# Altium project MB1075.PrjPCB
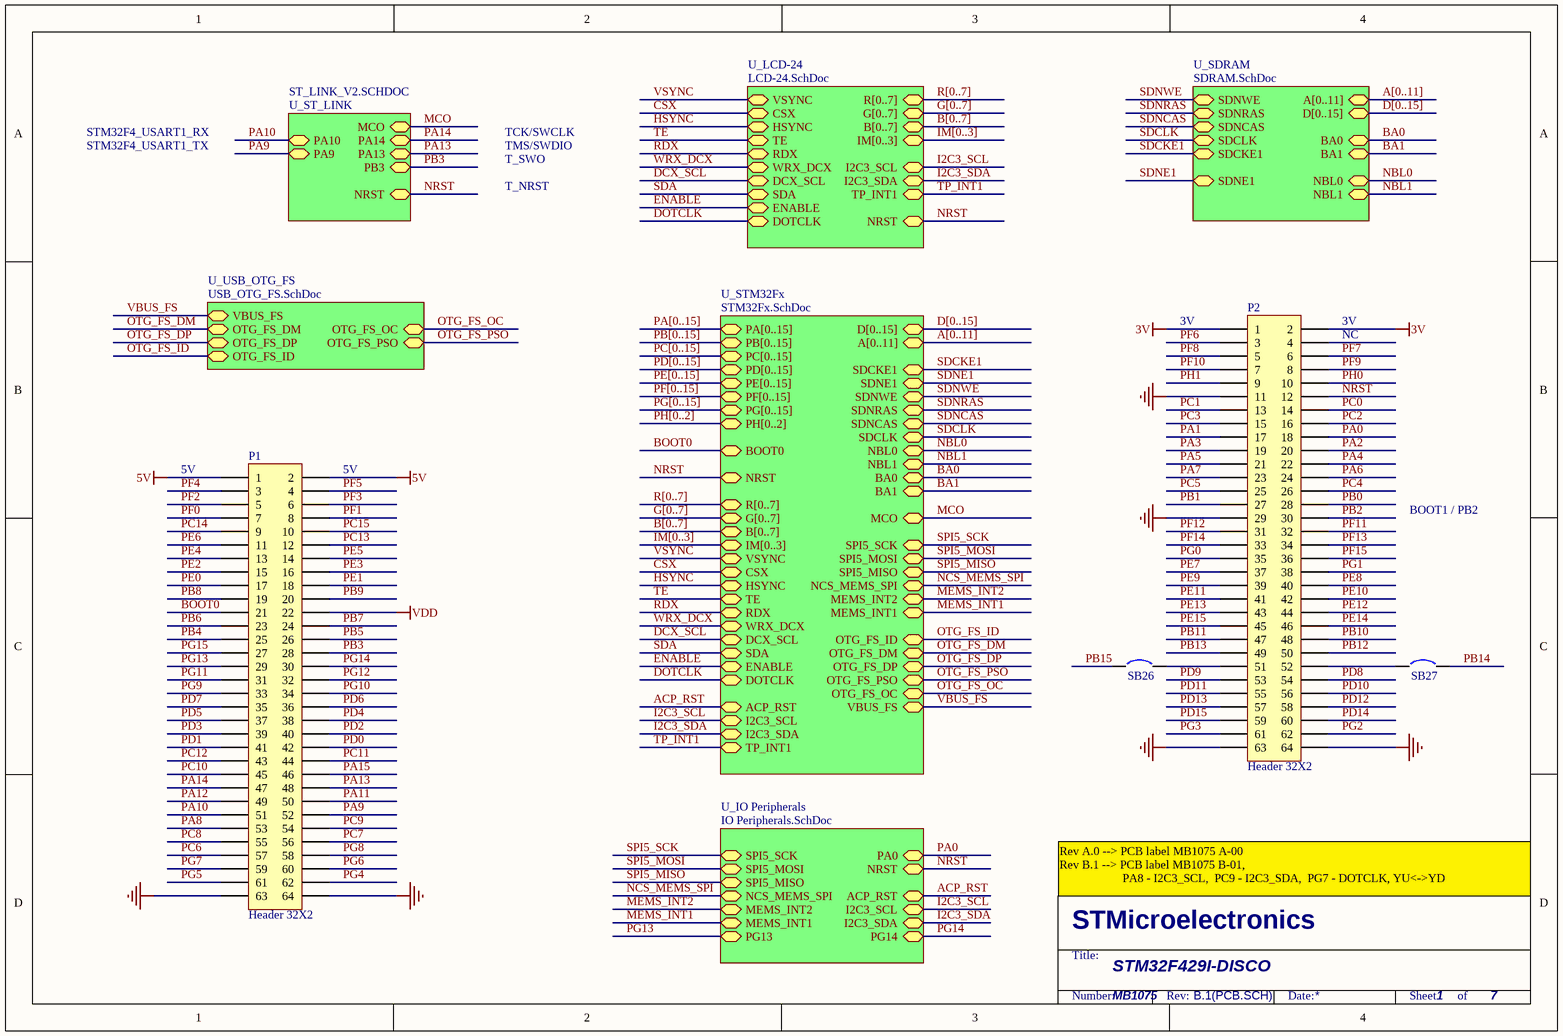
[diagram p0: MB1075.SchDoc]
7 sheets, 189 parts. Net scope: hierarchical (ports join the sheet entries above them; power ports are global).
Sheets:
  MB1075.SchDoc
    U_SDRAM = SDRAM.SchDoc
    U_IO Peripherals = IO Peripherals.SchDoc
    U_STM32Fx = STM32Fx.SchDoc
    U_USB_OTG_FS = USB_OTG_FS.SchDoc
    U_ST_LINK = ST_LINK_V2.SCHDOC
    U_LCD-24 = LCD-24.SchDoc

## Sheet MB1075.SchDoc
size A4; DocumentNumber: 1; Revision: B.1(PCB.SCH); SheetNumber: 1; SheetTotal: 7; PageSetup: Record=PageOptions|CenterHorizontal=True|CenterVertical=True|PrintScale=1.00|XCorrection=1.00|YCorrection=1.00|PrintKind=1|BorderSize=5000000|LeftOffset=0|BottomOffset=0|Orientation=2|PaperLength=1000|PaperWidth=1000|Scale=100|PaperSource=15|PrintQuality=1200|MediaType=1|DitherType=10|PaperKind=A4|PrintScaleMode=1

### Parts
P1  Header 32X2  [HDR2X32]
P2  Header 32X2  [HDR2X32]
SB26  Circuit Breaker  [JP2_SMD]  (value not drawn)
SB27  Circuit Breaker  [JP2_SMD]  (value not drawn)

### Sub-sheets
U_IO Peripherals = IO Peripherals.SchDoc: PA0, NRST, MEMS_INT1, NCS_MEMS_SPI, MEMS_INT2, SPI5_SCK, SPI5_MISO, SPI5_MOSI, ACP_RST, I2C3_SCL, I2C3_SDA, PG13, PG14
U_LCD-24 = LCD-24.SchDoc: NRST, B[0..7], G[0..7], R[0..7], IM[0..3], TP_INT1, VSYNC, CSX, HSYNC, TE, WRX_DCX, RDX, ENABLE, DCX_SCL, SDA, I2C3_SCL, I2C3_SDA, DOTCLK
U_SDRAM = SDRAM.SchDoc: A[0..11], D[0..15], SDNE1, NBL1, NBL0, SDNWE, SDNRAS, SDNCAS, SDCLK, SDCKE1, BA0, BA1
U_ST_LINK = ST_LINK_V2.SCHDOC: PA13, PA14, NRST, PB3, MCO, PA10, PA9
U_STM32Fx = STM32Fx.SchDoc: BOOT0, NRST, MCO, D[0..15], A[0..11], SDCKE1, SDNE1, SDNWE, NBL0, SDNRAS, NBL1, SDCLK, SDNCAS, BA0, BA1, PA[0..15], PB[0..15], PC[0..15], PD[0..15], PE[0..15], PH[0..2], PF[0..15], PG[0..15], R[0..7], G[0..7], B[0..7], IM[0..3], TP_INT1, VSYNC, CSX, HSYNC, TE, WRX_DCX, RDX, ENABLE, DCX_SCL, SDA, I2C3_SCL, I2C3_SDA, ACP_RST, MEMS_INT1, NCS_MEMS_SPI, MEMS_INT2, SPI5_SCK, SPI5_MISO, SPI5_MOSI, OTG_FS_ID, OTG_FS_DM, OTG_FS_DP, OTG_FS_PSO, OTG_FS_OC, VBUS_FS, DOTCLK
U_USB_OTG_FS = USB_OTG_FS.SchDoc: OTG_FS_PSO, OTG_FS_OC, OTG_FS_DM, OTG_FS_DP, OTG_FS_ID, VBUS_FS

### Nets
3V: P2.1 P2.2
5V: P1.1 P1.2
GND: P1.63 P1.64 P2.11 P2.29 P2.63 P2.64
VDD: P1.22
ACP_RST: P2.23 ; sheet U_IO Peripherals/ACP_RST, sheet U_STM32Fx/ACP_RST  [also labelled PA7]
BA0: P1.62 ; sheet U_SDRAM/BA0, sheet U_STM32Fx/BA0  [also labelled PG4]
BA1: P1.61 ; sheet U_SDRAM/BA1, sheet U_STM32Fx/BA1  [also labelled PG5]
BOOT0: P1.21 ; sheet U_STM32Fx/BOOT0
CSX: P2.16 ; sheet U_STM32Fx/CSX, sheet U_LCD-24/CSX  [also labelled PC2]
DCX_SCL: P2.6 ; sheet U_IO Peripherals/SPI5_SCK, sheet U_STM32Fx/DCX_SCL, sheet U_STM32Fx/SPI5_SCK, sheet U_LCD-24/DCX_SCL  [also labelled PF7, SPI5_SCK]
DOTCLK: P1.59 ; sheet U_STM32Fx/DOTCLK, sheet U_LCD-24/DOTCLK  [also labelled PG7]
ENABLE: P2.7 ; sheet U_STM32Fx/ENABLE, sheet U_LCD-24/ENABLE  [also labelled PF10]
HSYNC: P1.57 ; sheet U_STM32Fx/HSYNC, sheet U_LCD-24/HSYNC  [also labelled PC6]
I2C3_SCL: P1.53 ; sheet U_IO Peripherals/I2C3_SCL, sheet U_STM32Fx/I2C3_SCL, sheet U_LCD-24/I2C3_SCL  [also labelled PA8]
I2C3_SDA: P1.54 ; sheet U_IO Peripherals/I2C3_SDA, sheet U_STM32Fx/I2C3_SDA, sheet U_LCD-24/I2C3_SDA  [also labelled PC9]
MCO: sheet U_STM32Fx/MCO, sheet U_ST_LINK/MCO
MEMS_INT1: P2.17 ; sheet U_IO Peripherals/MEMS_INT1, sheet U_STM32Fx/MEMS_INT1  [also labelled PA1]
MEMS_INT2: P2.20 ; sheet U_IO Peripherals/MEMS_INT2, sheet U_STM32Fx/MEMS_INT2  [also labelled PA2]
NBL0: P1.17 ; sheet U_SDRAM/NBL0, sheet U_STM32Fx/NBL0  [also labelled PE0]
NBL1: P1.18 ; sheet U_SDRAM/NBL1, sheet U_STM32Fx/NBL1  [also labelled PE1]
NCS_MEMS_SPI: P2.13 ; sheet U_IO Peripherals/NCS_MEMS_SPI, sheet U_STM32Fx/NCS_MEMS_SPI  [also labelled PC1]
NRST: P2.12 ; sheet U_IO Peripherals/NRST, sheet U_STM32Fx/NRST, sheet U_ST_LINK/NRST, sheet U_LCD-24/NRST
OTG_FS_DM: SB27.2 ; sheet U_STM32Fx/OTG_FS_DM, sheet U_USB_OTG_FS/OTG_FS_DM  [also labelled PB14]
OTG_FS_DP: SB26.1 ; sheet U_STM32Fx/OTG_FS_DP, sheet U_USB_OTG_FS/OTG_FS_DP  [also labelled PB15]
OTG_FS_ID: P2.50 ; sheet U_STM32Fx/OTG_FS_ID, sheet U_USB_OTG_FS/OTG_FS_ID  [also labelled PB12]
OTG_FS_OC: P2.25 ; sheet U_STM32Fx/OTG_FS_OC, sheet U_USB_OTG_FS/OTG_FS_OC  [also labelled PC5]
OTG_FS_PSO: P2.26 ; sheet U_STM32Fx/OTG_FS_PSO, sheet U_USB_OTG_FS/OTG_FS_PSO  [also labelled PC4]
PA0: P2.18 ; sheet U_IO Peripherals/PA0
PA3: P2.19  [project net B5]
PA4: P2.22 ; sheet U_STM32Fx/VSYNC, sheet U_LCD-24/VSYNC  [also labelled VSYNC]
PA5: P2.21
PA6: P2.24  [project net G2]
PA9: P1.52 ; sheet U_ST_LINK/PA9
PA10: P1.51 ; sheet U_ST_LINK/PA10
PA11: P1.50
PA12: P1.49
PA13: P1.48 ; sheet U_ST_LINK/PA13
PA14: P1.47 ; sheet U_ST_LINK/PA14
PA15: P1.46 ; sheet U_STM32Fx/TP_INT1, sheet U_LCD-24/TP_INT1  [also labelled TP_INT1]
PB0: P2.28
PB1: P2.27
PB2: P2.30
PB3: P1.28 ; sheet U_ST_LINK/PB3
PB4: P1.25
PB5: P1.26 ; sheet U_SDRAM/SDCKE1, sheet U_STM32Fx/SDCKE1  [also labelled SDCKE1]
PB6: P1.23 ; sheet U_SDRAM/SDNE1, sheet U_STM32Fx/SDNE1  [also labelled SDNE1]
PB7: P1.24
PB8: P1.19  [project net B6]
PB9: P1.20  [project net B7]
PB10: P2.48  [project net G4]
PB11: P2.47  [project net G5]
PB13: P2.49 ; sheet U_STM32Fx/VBUS_FS, sheet U_USB_OTG_FS/VBUS_FS  [also labelled VBUS_FS]
PC0: P2.14 ; sheet U_SDRAM/SDNWE, sheet U_STM32Fx/SDNWE  [also labelled SDNWE]
PC3: P2.15
PC7: P1.56  [project net G6]
PC8: P1.55
PC10: P1.45
PC11: P1.44
PC12: P1.43
PC13: P1.12
PC14: P1.9
PC15: P1.10
PD0: P1.42  [project net D2]
PD1: P1.41  [project net D3]
PD2: P1.40
PD3: P1.39  [project net G7]
PD4: P1.38
PD5: P1.37
PD6: P1.36  [project net B2]
PD7: P1.35
PD8: P2.54  [project net D13]
PD9: P2.53  [project net D14]
PD10: P2.56  [project net D15]
PD11: P2.55 ; sheet U_STM32Fx/TE, sheet U_LCD-24/TE  [also labelled TE]
PD12: P2.58 ; sheet U_STM32Fx/RDX, sheet U_LCD-24/RDX  [also labelled RDX]
PD13: P2.57 ; sheet U_STM32Fx/WRX_DCX, sheet U_LCD-24/WRX_DCX  [also labelled WRX_DCX]
PD14: P2.60  [project net D0]
PD15: P2.59  [project net D1]
PE2: P1.15
PE3: P1.16
PE4: P1.13
PE5: P1.14
PE6: P1.11
PE7: P2.37  [project net D4]
PE8: P2.40  [project net D5]
PE9: P2.39  [project net D6]
PE10: P2.42  [project net D7]
PE11: P2.41  [project net D8]
PE12: P2.44  [project net D9]
PE13: P2.43  [project net D10]
PE14: P2.46  [project net D11]
PE15: P2.45  [project net D12]
PF0: P1.7  [project net A0]
PF1: P1.8  [project net A1]
PF2: P1.5  [project net A2]
PF3: P1.6  [project net A3]
PF4: P1.3  [project net A4]
PF5: P1.4  [project net A5]
PF6: P2.3
PF8: P2.5 ; sheet U_IO Peripherals/SPI5_MISO, sheet U_STM32Fx/SPI5_MISO  [also labelled SPI5_MISO]
PF9: P2.8 ; sheet U_IO Peripherals/SPI5_MOSI, sheet U_STM32Fx/SDA, sheet U_STM32Fx/SPI5_MOSI, sheet U_LCD-24/SDA  [also labelled SDA, SPI5_MOSI]
PF11: P2.32 ; sheet U_SDRAM/SDNRAS, sheet U_STM32Fx/SDNRAS  [also labelled SDNRAS]
PF12: P2.31  [project net A6]
PF13: P2.34  [project net A7]
PF14: P2.33  [project net A8]
PF15: P2.36  [project net A9]
PG0: P2.35  [project net A10]
PG1: P2.38  [project net A11]
PG2: P2.62
PG3: P2.61
PG6: P1.60
PG8: P1.58 ; sheet U_SDRAM/SDCLK, sheet U_STM32Fx/SDCLK  [also labelled SDCLK]
PG9: P1.33
PG10: P1.34  [project net G3]
PG11: P1.31  [project net B3]
PG12: P1.32  [project net B4]
PG13: P1.29 ; sheet U_IO Peripherals/PG13
PG14: P1.30 ; sheet U_IO Peripherals/PG14
PG15: P1.27 ; sheet U_SDRAM/SDNCAS, sheet U_STM32Fx/SDNCAS  [also labelled SDNCAS]
PH0: P2.10
PH1: P2.9
NetP2_51: P2.51 SB26.2
NetP2_52: P2.52 SB27.1

Not connected (* = marked no-connect by the designer): P2 4

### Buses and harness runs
bus A[0..11] = sheet U_SDRAM/A[0..11]
bus A[0..11] = sheet U_STM32Fx/A[0..11]
bus B[0..7] = sheet U_LCD-24/B[0..7]
bus B[0..7] = sheet U_STM32Fx/B[0..7]
bus D[0..15] = sheet U_SDRAM/D[0..15]
bus D[0..15] = sheet U_STM32Fx/D[0..15]
bus G[0..7] = sheet U_LCD-24/G[0..7]
bus G[0..7] = sheet U_STM32Fx/G[0..7]
bus IM[0..3] = sheet U_LCD-24/IM[0..3]
bus IM[0..3] = sheet U_STM32Fx/IM[0..3]
bus PA[0..15] = sheet U_STM32Fx/PA[0..15]
bus PB[0..15] = sheet U_STM32Fx/PB[0..15]
bus PC[0..15] = sheet U_STM32Fx/PC[0..15]
bus PD[0..15] = sheet U_STM32Fx/PD[0..15]
bus PE[0..15] = sheet U_STM32Fx/PE[0..15]
bus PF[0..15] = sheet U_STM32Fx/PF[0..15]
bus PG[0..15] = sheet U_STM32Fx/PG[0..15]
bus PH[0..2] = sheet U_STM32Fx/PH[0..2]
bus R[0..7] = sheet U_LCD-24/R[0..7]
bus R[0..7] = sheet U_STM32Fx/R[0..7]

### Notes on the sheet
- STM32F4_USART1_TX
- STM32F4_USART1_RX
- TCK/SWCLK
- TMS/SWDIO
- T_SWO
- T_NRST
- 3V
- (near P2) NC
- (near P2) 3V
- 5V
- (near P1) 5V
- BOOT1 / PB2
- Rev A.0 --> PCB label MB1075 A-00
  Rev B.1 --> PCB label MB1075 B-01,
  PA8 - I2C3_SCL,  PC9 - I2C3_SDA,  PG7 - DOTCLK, YU<->YD
- STM32F429I-DISCO
- MB1075

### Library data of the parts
P1 P2 = Header 32X2: Header, 32-Pin, Dual row
SB26 SB27 = Circuit Breaker: Solder: NO

## Sheet SDRAM.SchDoc
size A4; DocumentNumber: 4; Revision: B.1(PCB.SCH); SheetNumber: 4; SheetTotal: 7
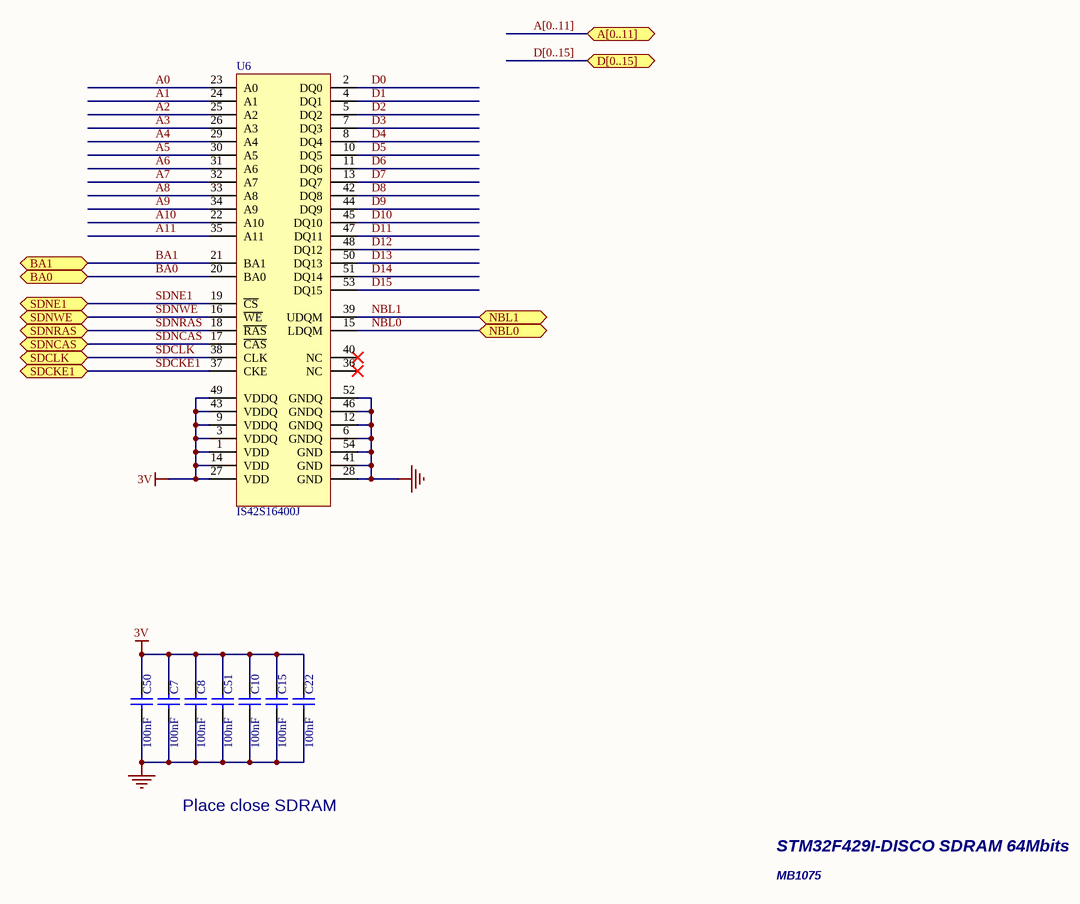
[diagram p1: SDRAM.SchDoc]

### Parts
C7  100nF  [0402C]
C8  100nF  [0402C]
C10  100nF  [0402C]
C15  100nF  [0402C]
C22  100nF  [0402C]
C50  100nF  [0402C]
C51  100nF  [0402C]
U6  IS42S16400J  [TSOP54-II]

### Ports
A[0..11], BA0, BA1, D[0..15], NBL0, NBL1, SDCKE1, SDCLK, SDNCAS, SDNE1, SDNRAS, SDNWE

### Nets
3V: C7.2 C8.2 C10.2 C15.2 C22.2 C50.2 C51.2 U6.1(VDD) U6.3(VDDQ) U6.9(VDDQ) U6.14(VDD) U6.27(VDD) U6.43(VDDQ) U6.49(VDDQ)
GND: C7.1 C8.1 C10.1 C15.1 C22.1 C50.1 C51.1 U6.6(GNDQ) U6.12(GNDQ) U6.28(GND) U6.41(GND) U6.46(GNDQ) U6.52(GNDQ) U6.54(GND)
A0: U6.23(A0)
A1: U6.24(A1)
A2: U6.25(A2)
A3: U6.26(A3)
A4: U6.29(A4)
A5: U6.30(A5)
A6: U6.31(A6)
A7: U6.32(A7)
A8: U6.33(A8)
A9: U6.34(A9)
A10: U6.22(A10)
A11: U6.35(A11)
BA0: U6.20(BA0) ; port BA0
BA1: U6.21(BA1) ; port BA1
D0: U6.2(DQ0)
D1: U6.4(DQ1)
D2: U6.5(DQ2)
D3: U6.7(DQ3)
D4: U6.8(DQ4)
D5: U6.10(DQ5)
D6: U6.11(DQ6)
D7: U6.13(DQ7)
D8: U6.42(DQ8)
D9: U6.44(DQ9)
D10: U6.45(DQ10)
D11: U6.47(DQ11)
D12: U6.48(DQ12)
D13: U6.50(DQ13)
D14: U6.51(DQ14)
D15: U6.53(DQ15)
NBL0: U6.15(LDQM) ; port NBL0
NBL1: U6.39(UDQM) ; port NBL1
SDCKE1: U6.37(CKE) ; port SDCKE1  [project net PB5]
SDCLK: U6.38(CLK) ; port SDCLK  [project net PG8]
SDNCAS: U6.17(~{CAS}) ; port SDNCAS  [project net PG15]
SDNE1: U6.19(~{CS}) ; port SDNE1  [project net PB6]
SDNRAS: U6.18(~{RAS}) ; port SDNRAS  [project net PF11]
SDNWE: U6.16(~{WE}) ; port SDNWE  [project net PC0]

Not connected (* = marked no-connect by the designer): U6 36(NC)* 40(NC)*

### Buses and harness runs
bus A[0..11] = port A[0..11]
bus D[0..15] = port D[0..15]

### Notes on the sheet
- Place close SDRAM
- STM32F429I-DISCO SDRAM 64Mbits
- MB1075

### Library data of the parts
C7 C8 C10 C15 C22 C50 C51 = Capacitor_ST: Capacitor 0402 / 0603 / 0805
U6 = IS45S16400J: SYNCHRONOUS DYNAMIC RAM, 1 Meg Bits x 16 Bits x 4 Banks (64-MBIT); Manuf_1: ISSI; Order: IS42S16400J-7TL; ECCN_US/EU: EAR99/NEC

## Sheet IO Peripherals.SchDoc
size A4; DocumentNumber: 6; Revision: B.1(PCB.SCH); SheetNumber: 6; SheetTotal: 7
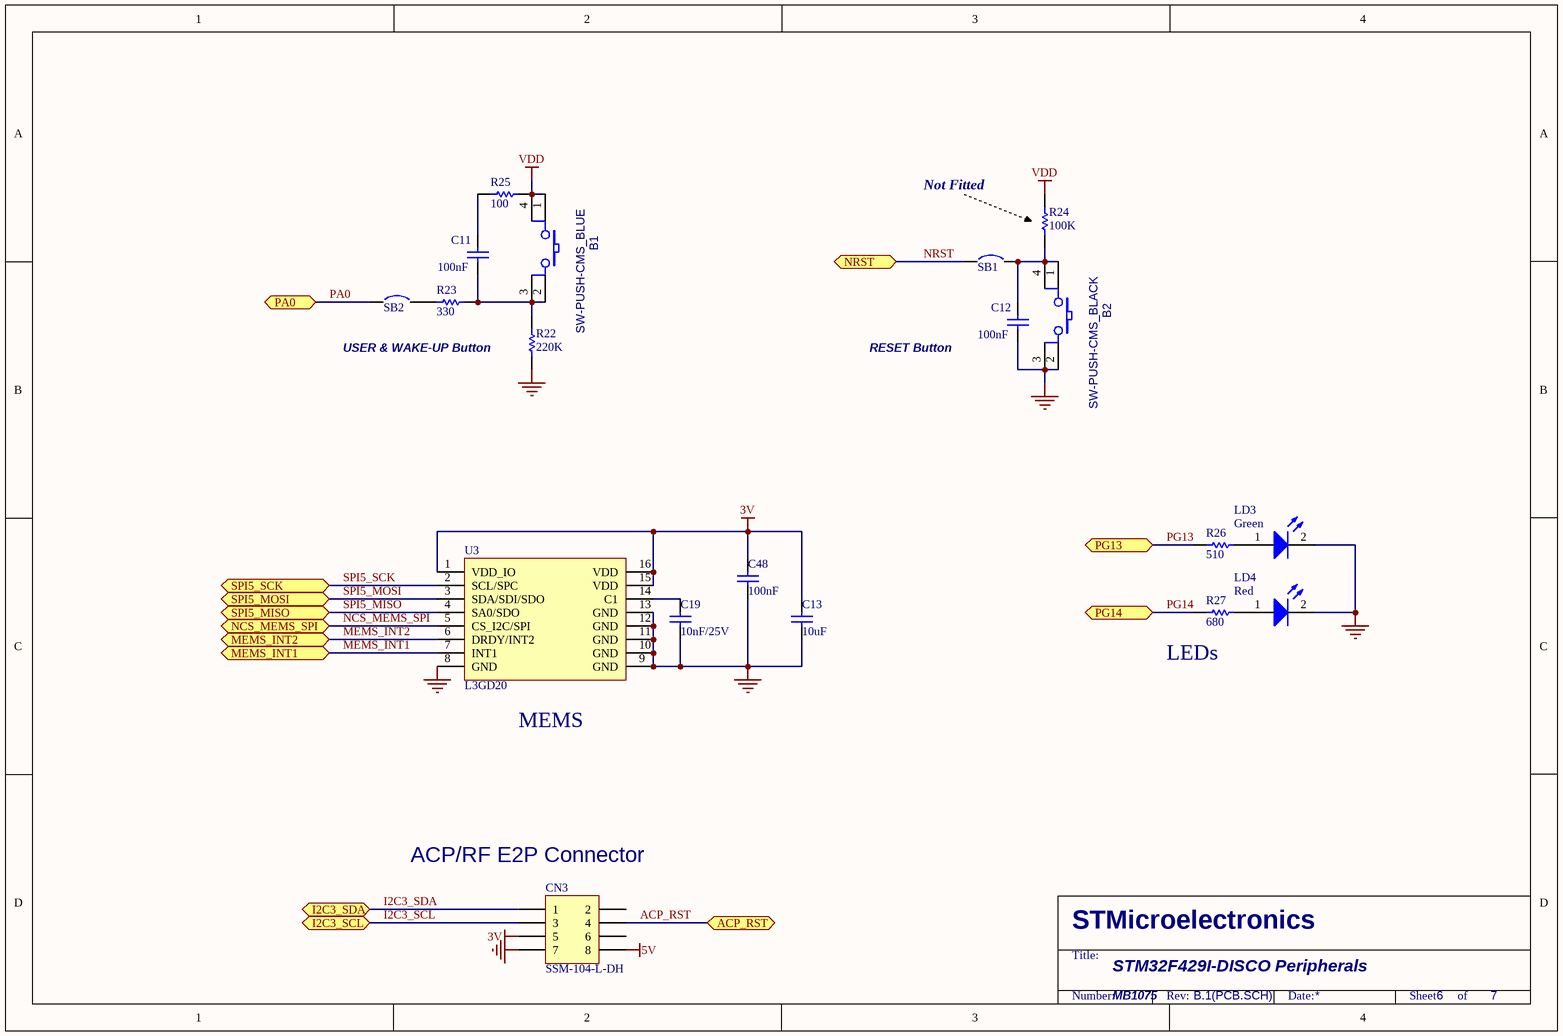
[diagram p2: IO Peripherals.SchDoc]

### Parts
B1  SW-PUSH-CMS_BLUE  [BP1CMS]
B2  SW-PUSH-CMS_BLACK  [BP1CMS]
C11  100nF  [0402C]
C12  100nF  [0402C]
C13  10uF  [0603C]
C19  10nF/25V  [0603C]
C48  100nF  [0402C]
CN3  SSM-104-L-DH  [SSM-104-L-DH]
LD3  Green  [0603D]
LD4  Red  [0603D]
R22  220K  [0402R]
R23  330  [0402R]
R24  100K  [0402R]
R25  100  [0402R]
R26  510  [0603R]
R27  680  [0603R]
SB1  Circuit Breaker  [JP2_SMD]  (value not drawn)
SB2  Circuit Breaker  [JP2_SMD]  (value not drawn)
U3  L3GD20  [LGA16-4x4]

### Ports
ACP_RST, I2C3_SCL, I2C3_SDA, MEMS_INT1, MEMS_INT2, NCS_MEMS_SPI, NRST, PA0, PG13, PG14, SPI5_MISO, SPI5_MOSI, SPI5_SCK

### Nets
3V: C13.2 C48.2 CN3.5 U3.1(VDD_IO) U3.15(VDD) U3.16(VDD)
5V: CN3.8
GND: B2.2 B2.3 C12.1 C13.1 C19.1 C48.1 CN3.7 LD3.2(K) LD4.2(K) R22.1 U3.8(GND) U3.9(GND) U3.10(GND) U3.11(GND) U3.12(GND) U3.13(GND)
VDD: B1.1 B1.4 R24.2 R25.2
ACP_RST: CN3.4 ; port ACP_RST
I2C3_SCL: CN3.3 ; port I2C3_SCL
I2C3_SDA: CN3.1 ; port I2C3_SDA
MEMS_INT1: U3.7(INT1) ; port MEMS_INT1
MEMS_INT2: U3.6(DRDY/INT2) ; port MEMS_INT2
NCS_MEMS_SPI: U3.5(CS_I2C/SPI) ; port NCS_MEMS_SPI
NRST: SB1.1 ; port NRST
PA0: SB2.1 ; port PA0
PG13: R26.1 ; port PG13
PG14: R27.1 ; port PG14
SPI5_MISO: U3.4(SA0/SDO) ; port SPI5_MISO  [project net PF8]
SPI5_MOSI: U3.3(SDA/SDI/SDO) ; port SPI5_MOSI  [project net PF9]
SPI5_SCK: U3.2(SCL/SPC) ; port SPI5_SCK  [project net DCX_SCL]
NetB1_2: B1.2 B1.3 C11.1 R22.2 R23.2
NetB2_1: B2.1 B2.4 C12.2 R24.1 SB1.2
NetC11_2: C11.2 R25.1
NetC19_2: C19.2 U3.14(C1)
NetLD3_1: LD3.1(A) R26.2
NetLD4_1: LD4.1(A) R27.2
NetR23_1: R23.1 SB2.2

Not connected (* = marked no-connect by the designer): CN3 2 6

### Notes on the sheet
- Not Fitted
- USER & WAKE-UP Button
- RESET Button
- (near R27) LEDs
- (near U3) MEMS
- (near CN3) ACP/RF E2P Connector
- STM32F429I-DISCO Peripherals
- MB1075

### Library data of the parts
B1 = SW-PUSH-CMS_BLUE: Non-Open Push-Button 0.1A 24V; Manuf_2: FARNELL; Manuf_Part_2: 535-930; Manuf_1: wealthmetal; Manuf_Part_1: TD0341X-G01-BLU; Ref St: 9180120; Description: Non-Open Push Button,Blue 0.1A 24V,Square head,6*6,SMT,180Degree,TD-0341X-GO1,wealthmetal
B2 = SW-PUSH-CMS_BLACK: Non-Open Push-Button 0.1A 24V; Manuf_2: FARNELL; Manuf_Part_2: 535-930; Manuf_1: wealthmetal; Manuf_Part_1: TD0341X-G01-BLA; Ref St: 9180120; Description: Non-Open Push Button,Black 0.1A 24V,Square head,6*6,SMT,180Degree,TD-0341X-GO1,wealthmetal
C11 C12 C48 = Capacitor_ST: Capacitor 0402 / 0603 / 0805
C13 C19 = CAP: Capacitor; Value: 100nF
CN3 = SSM-104-L-DH: Header, 5-Pin, Dual row
LD3 LD4 = LED2: Typical RED, GREEN, YELLOW, AMBER GaAs LED
R22-R27 = Resistor_ST: Resistor 0402 / 0603 / 0805; Description: Resistor 0402 or 0603 or 0805; Value: 10K
SB1 SB2 = Circuit Breaker: Solder: YES
U3 = L3GD20: MEMS motion sensor three-axis digital output gyroscopeelerometer; Manuf_1: STM; Manuf_Part_1: L3GD20TR; Provided: ST; Ref St: 9177042; ECCN_US/EU: EAR99/NEC

## Sheet STM32Fx.SchDoc
size A4; DocumentNumber: 5; Revision: B.1(PCB.SCH); SheetNumber: 5; SheetTotal: 7
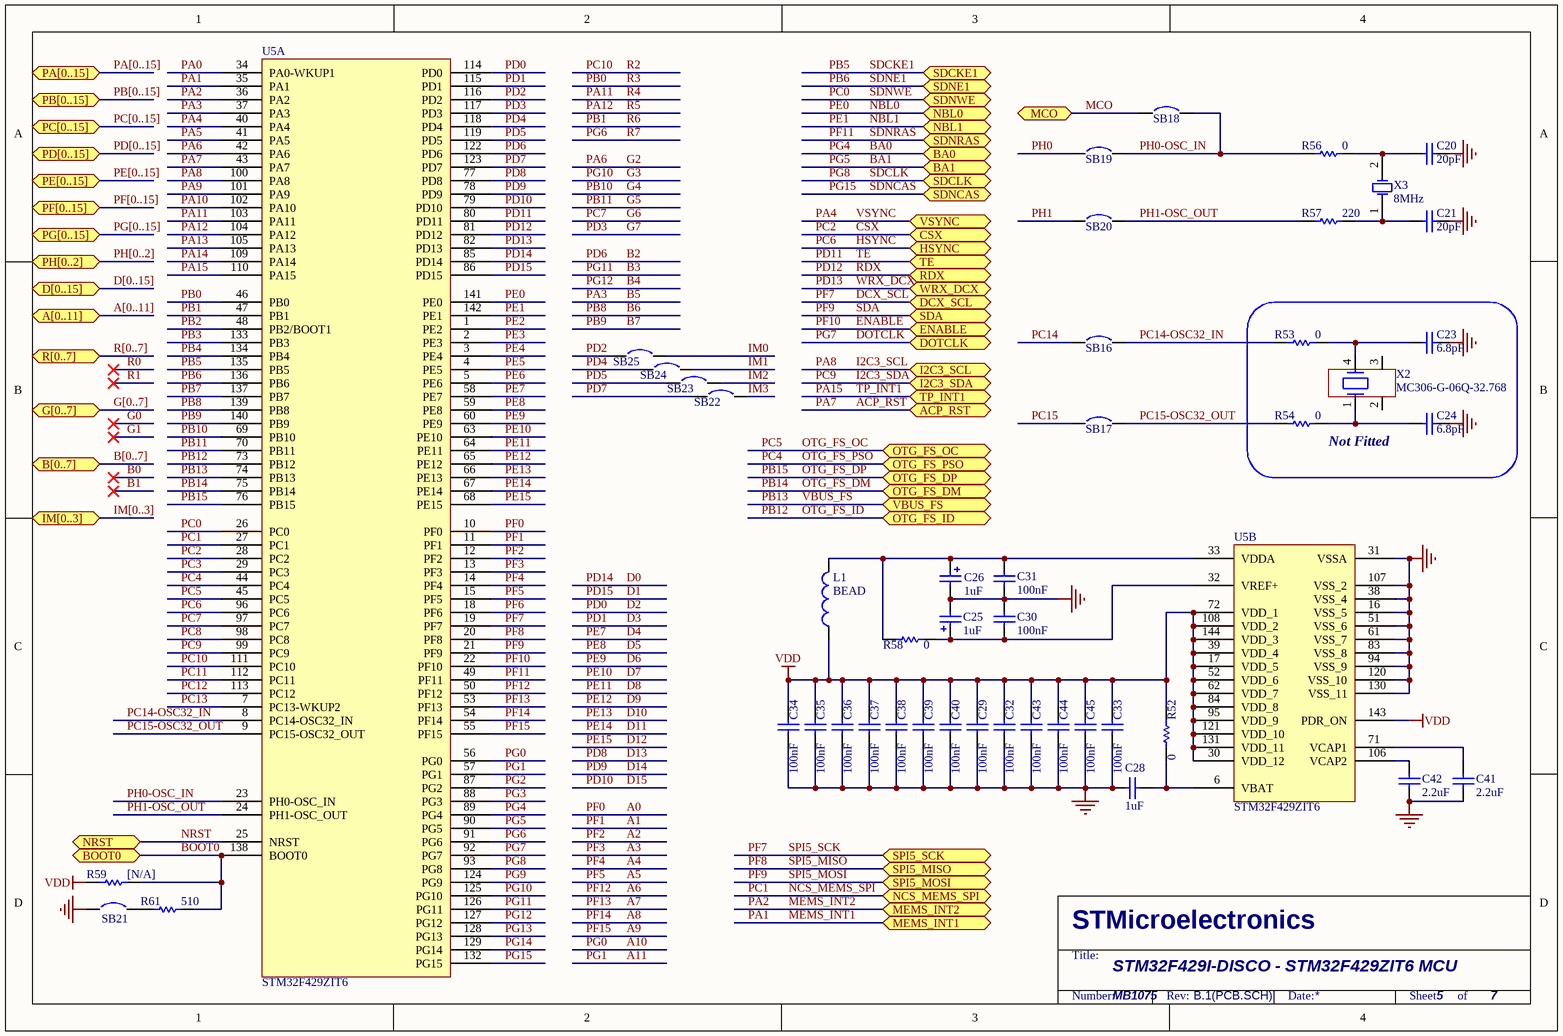
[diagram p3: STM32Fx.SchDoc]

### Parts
C20  20pF  [0402C]
C21  20pF  [0402C]
C23  6.8pF  [0402C]
C24  6.8pF  [0402C]
C25  1uF  [TAN-A]
C26  1uF  [TAN-A]
C28  1uF  [0603C]
C29  100nF  [0402C]
C30  100nF  [0402C]
C31  100nF  [0402C]
C32  100nF  [0402C]
C33  100nF  [0402C]
C34  100nF  [0402C]
C35  100nF  [0402C]
C36  100nF  [0402C]
C37  100nF  [0402C]
C38  100nF  [0402C]
C39  100nF  [0402C]
C40  100nF  [0402C]
C41  2.2uF  [TAN-A]
C42  2.2uF  [TAN-A]
C43  100nF  [0402C]
C44  100nF  [0402C]
C45  100nF  [0402C]
L1  BEAD  [0603L]
R52  0  [0402R]
R53  0  [0402R]
R54  0  [0402R]
R56  0  [0402R]
R57  220  [0402R]
R58  0  [0402R]
R59  [N/A]  [0402R]
R61  510  [0402R]
SB16  Circuit Breaker  [JP2_SMD]  (value not drawn)
SB17  Circuit Breaker  [JP2_SMD]  (value not drawn)
SB18  Circuit Breaker  [JP2_SMD]  (value not drawn)
SB19  Circuit Breaker  [JP2_SMD]  (value not drawn)
SB20  Circuit Breaker  [JP2_SMD]  (value not drawn)
SB21  Circuit Breaker  [JP2_SMD]  (value not drawn)
SB22  Circuit Breaker  [JP2_SMD]  (value not drawn)
SB23  Circuit Breaker  [JP2_SMD]  (value not drawn)
SB24  Circuit Breaker  [JP2_SMD]  (value not drawn)
SB25  Circuit Breaker  [JP2_SMD]  (value not drawn)
U5  STM32F429ZIT6  [TQFP144]  (parts A,B of 2)
X2  MC306-G-06Q-32.768  [MC306-CRYSTAL]
X3  8MHz  [XTAL1]

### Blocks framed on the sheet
Not Fitted: C23 C24 R53 R54 X2

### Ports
A[0..11], ACP_RST, B[0..7], BA0, BA1, BOOT0, CSX, D[0..15], DCX_SCL, DOTCLK, ENABLE, G[0..7], HSYNC, I2C3_SCL, I2C3_SDA, IM[0..3], MCO, MEMS_INT1, MEMS_INT2, NBL0, NBL1, NCS_MEMS_SPI, NRST, OTG_FS_DM, OTG_FS_DP, OTG_FS_ID, OTG_FS_OC, OTG_FS_PSO, PA[0..15], PB[0..15], PC[0..15], PD[0..15], PE[0..15], PF[0..15], PG[0..15], PH[0..2], R[0..7], RDX, SDA, SDCKE1, SDCLK, SDNCAS, SDNE1, SDNRAS, SDNWE, SPI5_MISO, SPI5_MOSI, SPI5_SCK, TE, TP_INT1, VBUS_FS, VSYNC, WRX_DCX

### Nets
GND: C20.2 C21.2 C23.2 C24.2 C25.2 C26.2 C28.1 C29.1 C30.2 C31.1 C32.1 C33.1 C34.1 C35.1 C36.1 C37.1 C38.1 C39.1 C40.1 C41.2 C42.2 C43.1 C44.1 C45.1 SB21.1 U5.16(VSS_5) U5.31(VSSA) U5.38(VSS_4) U5.51(VSS_6) U5.61(VSS_7) U5.83(VSS_8) U5.94(VSS_9) U5.107(VSS_2) U5.120(VSS_10) U5.130(VSS_11)
VDD: C29.2 C32.2 C33.2 C34.2 C35.2 C36.2 C37.2 C38.2 C39.2 C40.2 C43.2 C44.2 C45.2 L1.1 R52.2 R59.1 U5.17(VDD_5) U5.30(VDD_12) U5.39(VDD_4) U5.52(VDD_6) U5.62(VDD_7) U5.72(VDD_1) U5.84(VDD_8) U5.95(VDD_9) U5.108(VDD_2) U5.121(VDD_10) U5.131(VDD_11) U5.143(PDR_ON) U5.144(VDD_3)
A0: U5.10(PF0)  [also labelled PF0]
A1: U5.11(PF1)  [also labelled PF1]
A2: U5.12(PF2)  [also labelled PF2]
A3: U5.13(PF3)  [also labelled PF3]
A4: U5.14(PF4)  [also labelled PF4]
A5: U5.15(PF5)  [also labelled PF5]
A6: U5.50(PF12)  [also labelled PF12]
A7: U5.53(PF13)  [also labelled PF13]
A8: U5.54(PF14)  [also labelled PF14]
A9: U5.55(PF15)  [also labelled PF15]
A10: U5.56(PG0)  [also labelled PG0]
A11: U5.57(PG1)  [also labelled PG1]
ACP_RST: U5.43(PA7) ; port ACP_RST  [also labelled PA7]
B2: U5.122(PD6)  [also labelled PD6]
B3: U5.126(PG11)  [also labelled PG11]
B4: U5.127(PG12)  [also labelled PG12]
B5: U5.37(PA3)  [also labelled PA3]
B6: U5.139(PB8)  [also labelled PB8]
B7: U5.140(PB9)  [also labelled PB9]
BA0: U5.89(PG4) ; port BA0  [also labelled PG4]
BA1: U5.90(PG5) ; port BA1  [also labelled PG5]
BOOT0: R59.2 R61.2 U5.138(BOOT0) ; port BOOT0
CSX: U5.28(PC2) ; port CSX  [also labelled PC2]
D0: U5.85(PD14)  [also labelled PD14]
D1: U5.86(PD15)  [also labelled PD15]
D2: U5.114(PD0)  [also labelled PD0]
D3: U5.115(PD1)  [also labelled PD1]
D4: U5.58(PE7)  [also labelled PE7]
D5: U5.59(PE8)  [also labelled PE8]
D6: U5.60(PE9)  [also labelled PE9]
D7: U5.63(PE10)  [also labelled PE10]
D8: U5.64(PE11)  [also labelled PE11]
D9: U5.65(PE12)  [also labelled PE12]
D10: U5.66(PE13)  [also labelled PE13]
D11: U5.67(PE14)  [also labelled PE14]
D12: U5.68(PE15)  [also labelled PE15]
D13: U5.77(PD8)  [also labelled PD8]
D14: U5.78(PD9)  [also labelled PD9]
D15: U5.79(PD10)  [also labelled PD10]
DCX_SCL: U5.19(PF7) ; port DCX_SCL, port SPI5_SCK  [also labelled PF7, SPI5_SCK]
DOTCLK: U5.92(PG7) ; port DOTCLK  [also labelled PG7]
ENABLE: U5.22(PF10) ; port ENABLE  [also labelled PF10]
G2: U5.42(PA6)  [also labelled PA6]
G3: U5.125(PG10)  [also labelled PG10]
G4: U5.69(PB10)  [also labelled PB10]
G5: U5.70(PB11)  [also labelled PB11]
G6: U5.97(PC7)  [also labelled PC7]
G7: U5.117(PD3)  [also labelled PD3]
HSYNC: U5.96(PC6) ; port HSYNC  [also labelled PC6]
I2C3_SCL: U5.100(PA8) ; port I2C3_SCL  [also labelled PA8]
I2C3_SDA: U5.99(PC9) ; port I2C3_SDA  [also labelled PC9]
IM0: SB25.2
IM1: SB24.2
IM2: SB23.2
IM3: SB22.2
MCO: SB18.1 ; port MCO
MEMS_INT1: U5.35(PA1) ; port MEMS_INT1  [also labelled PA1]
MEMS_INT2: U5.36(PA2) ; port MEMS_INT2  [also labelled PA2]
NBL0: U5.141(PE0) ; port NBL0  [also labelled PE0]
NBL1: U5.142(PE1) ; port NBL1  [also labelled PE1]
NCS_MEMS_SPI: U5.27(PC1) ; port NCS_MEMS_SPI  [also labelled PC1]
NRST: U5.25(NRST) ; port NRST
OTG_FS_DM: U5.75(PB14) ; port OTG_FS_DM  [also labelled PB14]
OTG_FS_DP: U5.76(PB15) ; port OTG_FS_DP  [also labelled PB15]
OTG_FS_ID: U5.73(PB12) ; port OTG_FS_ID  [also labelled PB12]
OTG_FS_OC: U5.45(PC5) ; port OTG_FS_OC  [also labelled PC5]
OTG_FS_PSO: U5.44(PC4) ; port OTG_FS_PSO  [also labelled PC4]
PA0: U5.34(PA0-WKUP1)
PA4: U5.40(PA4) ; port VSYNC  [also labelled VSYNC]
PA5: U5.41(PA5)
PA9: U5.101(PA9)
PA10: U5.102(PA10)
PA11: U5.103(PA11)  [also labelled R4]
PA12: U5.104(PA12)  [also labelled R5]
PA13: U5.105(PA13)
PA14: U5.109(PA14)
PA15: U5.110(PA15) ; port TP_INT1  [also labelled TP_INT1]
PB0: U5.46(PB0)  [also labelled R3]
PB1: U5.47(PB1)  [also labelled R6]
PB2: U5.48(PB2/BOOT1)
PB3: U5.133(PB3)
PB4: U5.134(PB4)
PB5: U5.135(PB5) ; port SDCKE1  [also labelled SDCKE1]
PB6: U5.136(PB6) ; port SDNE1  [also labelled SDNE1]
PB7: U5.137(PB7)
PB13: U5.74(PB13) ; port VBUS_FS  [also labelled VBUS_FS]
PC0: U5.26(PC0) ; port SDNWE  [also labelled SDNWE]
PC3: U5.29(PC3)
PC8: U5.98(PC8)
PC10: U5.111(PC10)  [also labelled R2]
PC11: U5.112(PC11)
PC12: U5.113(PC12)
PC13: U5.7(PC13-WKUP2)
PC14: SB16.1
PC14-OSC32_IN: R53.1 SB16.2 U5.8(PC14-OSC32_IN)
PC15: SB17.1
PC15-OSC32_OUT: R54.1 SB17.2 U5.9(PC15-OSC32_OUT)
PD2: SB25.1 U5.116(PD2)
PD4: SB24.1 U5.118(PD4)
PD5: SB23.1 U5.119(PD5)
PD7: SB22.1 U5.123(PD7)
PD11: U5.80(PD11) ; port TE  [also labelled TE]
PD12: U5.81(PD12) ; port RDX  [also labelled RDX]
PD13: U5.82(PD13) ; port WRX_DCX  [also labelled WRX_DCX]
PE2: U5.1(PE2)
PE3: U5.2(PE3)
PE4: U5.3(PE4)
PE5: U5.4(PE5)
PE6: U5.5(PE6)
PF6: U5.18(PF6)
PF8: U5.20(PF8) ; port SPI5_MISO  [also labelled SPI5_MISO]
PF9: U5.21(PF9) ; port SDA, port SPI5_MOSI  [also labelled SDA, SPI5_MOSI]
PF11: U5.49(PF11) ; port SDNRAS  [also labelled SDNRAS]
PG2: U5.87(PG2)
PG3: U5.88(PG3)
PG6: U5.91(PG6)  [also labelled R7]
PG8: U5.93(PG8) ; port SDCLK  [also labelled SDCLK]
PG9: U5.124(PG9)
PG13: U5.128(PG13)
PG14: U5.129(PG14)
PG15: U5.132(PG15) ; port SDNCAS  [also labelled SDNCAS]
PH0: SB19.1
PH0-OSC_IN: R56.1 SB18.2 SB19.2 U5.23(PH0-OSC_IN)
PH1: SB20.1
PH1-OSC_OUT: R57.1 SB20.2 U5.24(PH1-OSC_OUT)
NetC20_1: C20.1 R56.2 X3.2(OSC2)
NetC21_1: C21.1 R57.2 X3.1(OSC1)
NetC23_1: C23.1 R53.2 X2.4
NetC24_1: C24.1 R54.2 X2.1
NetC25_1: C25.1 C30.1 R58.2 U5.32(VREF+)
NetC26_1: C26.1 C31.2 L1.2 R58.1 U5.33(VDDA)
NetC28_2: C28.2 R52.1 U5.6(VBAT)
NetC41_1: C41.1 U5.71(VCAP1)
NetC42_1: C42.1 U5.106(VCAP2)
NetR61_1: R61.1 SB21.2

Not connected (* = marked no-connect by the designer): X2 2 3

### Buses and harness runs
bus A[0..11] = port A[0..11]
bus B[0..7] = port B[0..7]
bus D[0..15] = port D[0..15]
bus G[0..7] = port G[0..7]
bus IM[0..3] = port IM[0..3]
bus PA[0..15] = port PA[0..15]
bus PB[0..15] = port PB[0..15]
bus PC[0..15] = port PC[0..15]
bus PD[0..15] = port PD[0..15]
bus PE[0..15] = port PE[0..15]
bus PF[0..15] = port PF[0..15]
bus PG[0..15] = port PG[0..15]
bus PH[0..2] = port PH[0..2]
bus R[0..7] = port R[0..7]

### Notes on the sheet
- STM32F429I-DISCO - STM32F429ZIT6 MCU
- MB1075

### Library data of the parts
C20 C21 C28 = Capacitor_ST: Capacitor 0402 / 0603 / 0805; Value: 100nF
C23 C24 = Capacitor_ST: Capacitor 0402 / 0603 / 0805; Value: 100nF; Fitted: NO
C25 C26 = Cap Pol1: Polarized Capacitor (Radial); Value: 10uF
C29-C40 C43-C45 = Capacitor_ST: Capacitor 0402 / 0603 / 0805
C41 C42 = Cap Low ESR: Low ESR Ceramic Capacitor (X7R); Order: CC1206KKX7R7BB225
L1 = Inductor: Manuf_Part_1: FCM1608KF-601T03; Value: 100uH
R52 R56-R58 R61 = Resistor_ST: as R22 on sheet IO Peripherals
R53 R54 R59 = Resistor_ST: Resistor 0402 / 0603 / 0805; Description: Resistor 0402 or 0603 or 0805; Value: 10K; Fitted: NO
SB16-SB18 SB20 SB21 = Circuit Breaker: Solder: YES
SB19 SB22-SB25 = Circuit Breaker: Solder: NO
U5 = STM32F429ZIT6U: STM32 Big Manta (STM32F429ZIT6U); Manuf_1: STM; Provided: ST; Ref St: 9175122; ECCN_US/EU: 3A991A2/NEC
X2 = XTAL_32K: Crystal oscillator for clock,32.768K,6PF,20PPM,-40~85 degree,SMT; Manuf_Part_1: ETMB32.768W060BMPF; Manuf_1: JFVNY; Description: crystal oscillator for clock,32.768K,6PF,20PPM,-40~85 degree,SMT,ETMB32.768W060BMPF; Fitted: NO
X3 = XTAL: Crystal Oscillator,8Mhz,20PF,20PPM,-10-70 degree,DIP,HC-49S; Manuf_Part_1: 9SL8000020AFXHF0

## Sheet USB_OTG_FS.SchDoc
size A4; DocumentNumber: 3; Revision: B.1(PCB.SCH); SheetNumber: 3; SheetTotal: 7
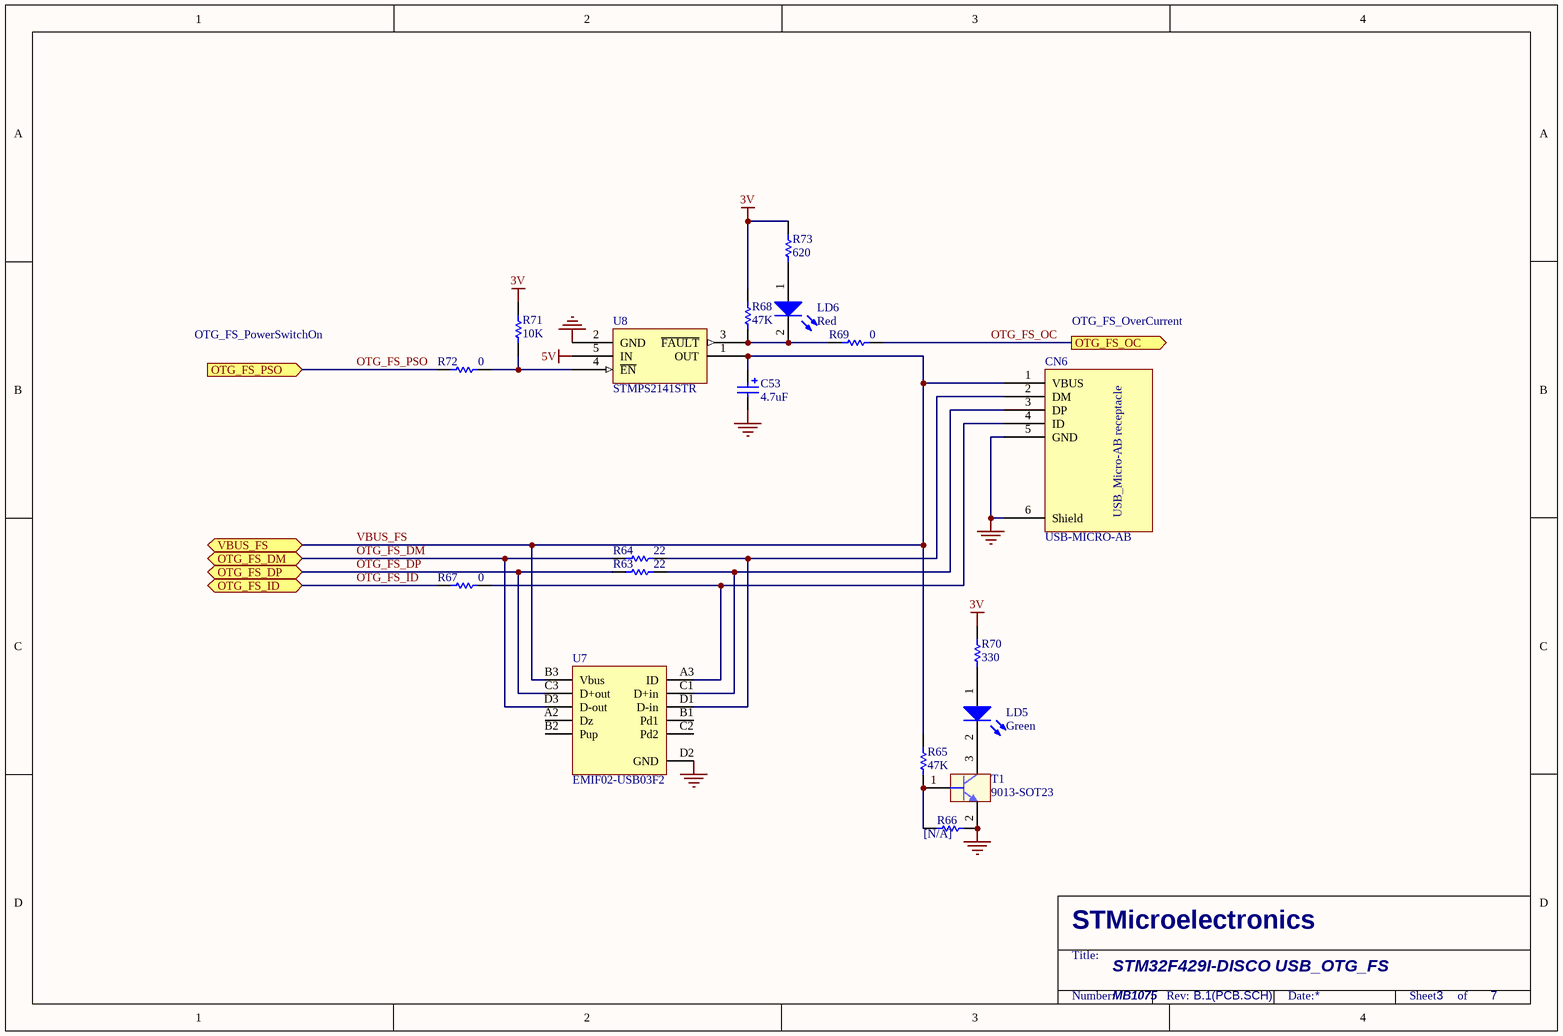
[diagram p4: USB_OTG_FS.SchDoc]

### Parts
C53  4.7uF  [TAN-A]
CN6  USB-MICRO-AB  [USB-MICRO-AB]
LD5  Green  [0603D]
LD6  Red  [0603D]
R63  22  [0402R]
R64  22  [0402R]
R65  47K  [0402R]
R66  [N/A]  [0402R]
R67  0  [0402R]
R68  47K  [0402R]
R69  0  [0402R]
R70  330  [0603R]
R71  10K  [0402R]
R72  0  [0402R]
R73  620  [0603R]
T1  9013-SOT23  [SOT-23]
U7  EMIF02-USB03F2  [Flip Chip]
U8  STMPS2141STR  [SOT23-5L]

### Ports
OTG_FS_DM, OTG_FS_DP, OTG_FS_ID, OTG_FS_OC, OTG_FS_PSO, VBUS_FS

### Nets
3V: R68.2 R70.2 R71.2 R73.2
5V: U8.5(IN)
GND: C53.2 CN6.5(GND) CN6.6(Shield) R66.2 T1.2(E) U7.D2(GND) U8.2(GND)
OTG_FS_DM: R64.1 U7.D3(D-out) ; port OTG_FS_DM
OTG_FS_DP: R63.1 U7.C3(D+out) ; port OTG_FS_DP
OTG_FS_ID: R67.1 ; port OTG_FS_ID
OTG_FS_OC: R69.2 ; port OTG_FS_OC
OTG_FS_PSO: R72.1 ; port OTG_FS_PSO
VBUS_FS: C53.1 CN6.1(VBUS) R65.2 U7.B3(Vbus) U8.1(OUT) ; port VBUS_FS  [project net PB13]
NetCN6_2: CN6.2(DM) R64.2 U7.D1(D-in)
NetCN6_3: CN6.3(DP) R63.2 U7.C1(D+in)
NetCN6_4: CN6.4(ID) R67.2 U7.A3(ID)
NetLD5_1: LD5.1(A) R70.1
NetLD5_2: LD5.2(K) T1.3(C)
NetLD6_1: LD6.1(A) R73.1
NetLD6_2: LD6.2(K) R68.1 R69.1 U8.3(~{FAULT})
NetR65_1: R65.1 R66.1 T1.1(B)
NetR71_1: R71.1 R72.2 U8.4(~{EN})

Not connected (* = marked no-connect by the designer): U7 A2(Dz) B1(Pd1) B2(Pup) C2(Pd2)

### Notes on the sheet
- OTG_FS_PowerSwitchOn
- OTG_FS_OverCurrent
- STM32F429I-DISCO USB_OTG_FS
- MB1075

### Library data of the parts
C53 = Cap Pol1: Polarized Capacitor (Radial); Value: 47uF
CN6 = USB-MICRO-AB: USB-MICRO-AB, 47590-0001, SMT, MOLEX; Ref St: xxxxxxx
LD5 LD6 = LED2: as LD3 on sheet IO Peripherals
R63-R65 R67-R70 R72 R73 = Resistor_ST: as R22 on sheet IO Peripherals
R66 = Resistor_ST: as R53 on sheet STM32Fx
R71 = Resistor_ST: Resistor 0402 / 0603 / 0805; Description: Resistor 0402 or 0603 or 0805
T1 = 9013-SOT23: NPN Bipolar Transistor; Description: NPN Bipolar Transistor, SOT-23 Footprint
U7 = EMIF02-USB03F2: 2-line IPAD, EMI filter including ESD protection; Manuf_1: STM; Provided: ST; ECCN_US/EU: EAR99/NEC; Ref St: 9179037
U8 = STMPS2141STR: Enhanced single channel power switches; Manuf_1: STM; Provided: ST; ECCN_US/EU: EAR99/NEC

## Sheet ST_LINK_V2.SCHDOC
size A4; DocumentNumber: 2; Revision: B.1(PCB.SCH); SheetNumber: 2; SheetTotal: 7
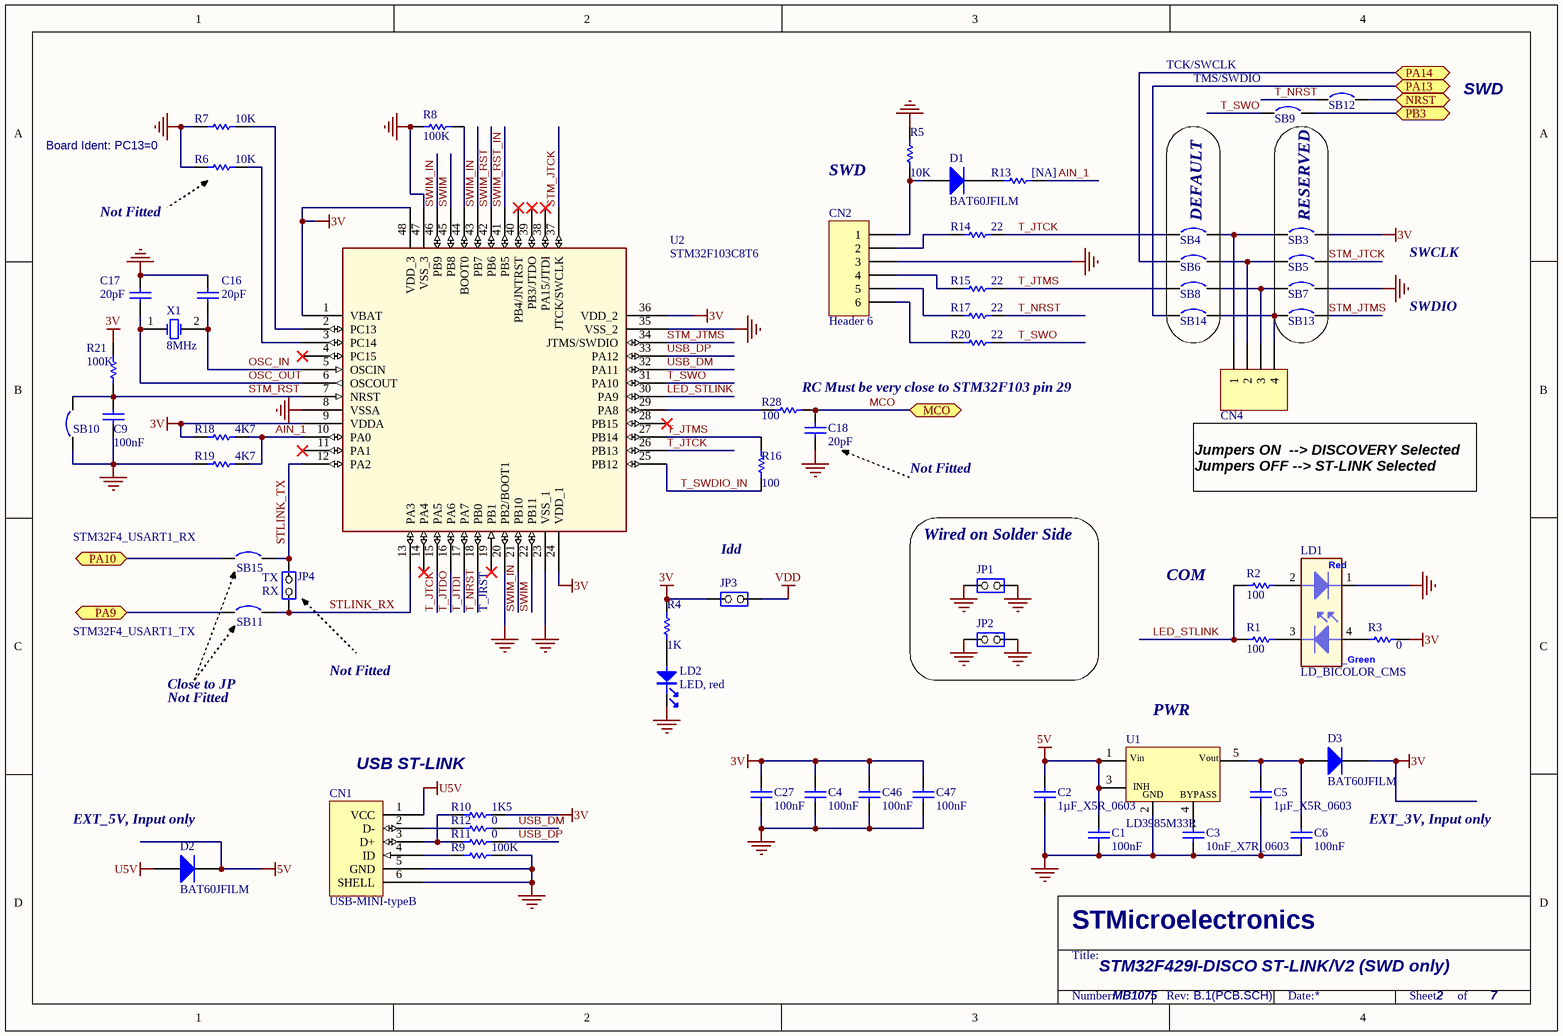
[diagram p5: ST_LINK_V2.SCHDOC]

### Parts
C1  100nF  [0402C]
C2  1µF_X5R_0603  [0603C]
C3  10nF_X7R_0603  [0603C]
C4  100nF  [0402C]
C5  1µF_X5R_0603  [0603C]
C6  100nF  [0402C]
C9  100nF  [0402C]
C16  20pF  [0402C]
C17  20pF  [0402C]
C18  20pF  [0402C]
C27  100nF  [0402C]
C46  100nF  [0402C]
C47  100nF  [0402C]
CN1  USB-MINI-typeB  [USB-MINI-B-SMD]
CN2  Header 6  [HDR1X6]
CN4  Header 4  [Header 4]  (value not drawn)
D1  BAT60JFILM  [SOD323/A]
D2  BAT60JFILM  [SOD323/A]
D3  BAT60JFILM  [SOD323/A]
JP1  (no value)  [SIP2/2.54]
JP2  (no value)  [SIP2/2.54]
JP3  (no value)  [SIP2/2.54]
JP4  JP2  [SIP2/2.54]  (value not drawn)
LD1  LD_BICOLOR_CMS  [HSMF-A201]
LD2  LED, red  [0603D]
R1  100  [0402R]
R2  100  [0402R]
R3  0  [0402R]
R4  1K  [0402R]
R5  10K  [0402R]
R6  10K  [0402R]
R7  10K  [0402R]
R8  100K  [0402R]
R9  100K  [0402R]
R10  1K5  [0402R]
R11  0  [0402R]
R12  0  [0402R]
R13  [NA]  [0402R]
R14  22  [0402R]
R15  22  [0402R]
R16  100  [0402R]
R17  22  [0402R]
R18  4K7  [0402R]
R19  4K7  [0402R]
R20  22  [0402R]
R21  100K  [0402R]
R28  100  [0402R]
SB3  Circuit Breaker  [JP2_SMD]  (value not drawn)
SB4  Circuit Breaker  [JP2_SMD]  (value not drawn)
SB5  Circuit Breaker  [JP2_SMD]  (value not drawn)
SB6  Circuit Breaker  [JP2_SMD]  (value not drawn)
SB7  Circuit Breaker  [JP2_SMD]  (value not drawn)
SB8  Circuit Breaker  [JP2_SMD]  (value not drawn)
SB9  Circuit Breaker  [JP2_SMD]  (value not drawn)
SB10  Circuit Breaker  [JP2_SMD]  (value not drawn)
SB11  Circuit Breaker  [JP2_SMD]  (value not drawn)
SB12  Circuit Breaker  [JP2_SMD]  (value not drawn)
SB13  Circuit Breaker  [JP2_SMD]  (value not drawn)
SB14  Circuit Breaker  [JP2_SMD]  (value not drawn)
SB15  Circuit Breaker  [JP2_SMD]  (value not drawn)
U1  LD3985M33R  [SOT-23-5L]
U2  STM32F103C8T6  [QFP48 7X7]
X1  8MHz  [XTAL1]

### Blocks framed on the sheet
DEFAULT: SB4 SB6 SB8 SB14
RESERVED: SB3 SB5 SB7 SB13
Wired on Solder Side: JP1 JP2

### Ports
MCO, NRST, PA9, PA10, PA13, PA14, PB3

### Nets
3V: C4.2 C27.2 C46.2 C47.2 D3.2(K) JP3.1(COMMON) R3.2 R4.2 R10.2 R18.1 R21.2 SB3.2 U2.1(VBAT) U2.9(VDDA) U2.24(VDD_1) U2.36(VDD_2) U2.48(VDD_3)
5V: C1.2 C2.2 D2.2(K) U1.1(Vin) U1.3(CE)
GND: C1.1 C2.1 C3.1 C4.1 C5.2 C6.1 C9.1 C16.2 C17.2 C18.1 C27.1 C46.1 C47.1 CN1.5(GND) CN1.6(SHELL) CN2.3 JP1.1(COMMON) JP1.2(NO) JP2.1(COMMON) JP2.2(NO) LD1.1 LD2.2 R5.2 R6.1 R7.1 R8.1 R9.2 R19.1 SB7.2 SB10.1 U1.2(GND) U2.8(VSSA) U2.20(PB2/BOOT1) U2.23(VSS_1) U2.35(VSS_2) U2.47(VSS_3)
U5V: CN1.1(VCC) D2.1(A)
VDD: JP3.2(NO)
AIN_1: R13.2 R18.2 R19.2 U2.10(PA0)
LED_STLINK: R1.1 R2.1 U2.30(PA9)
MCO: C18.2 R28.2 ; port MCO
NRST: SB12.2 ; port NRST
OSC_IN: C16.1 U2.5(OSCIN) X1.2(OSC2)
OSC_OUT: C17.1 U2.6(OSCOUT) X1.1(OSC1)
PA9: SB11.1 ; port PA9
PA10: SB15.1 ; port PA10
PA13: SB14.1 ; port PA13
PA14: SB6.1 ; port PA14
PB3: SB9.2 ; port PB3
STLINK_RX: JP4.1(COMMON) SB11.2 U2.13(PA3)
STLINK_TX: JP4.2(NO) SB15.2 U2.12(PA2)
STM_JTCK: SB5.2 U2.37(JTCK/SWCLK)
STM_JTMS: SB13.2 U2.34(JTMS/SWDIO)
STM_RST: C9.2 R21.1 SB10.2 U2.7(NRST)
SWIM: U2.22(PB11) U2.45(PB8)
SWIM_IN: U2.21(PB10) U2.43(PB7) U2.46(PB9)
SWIM_RST: U2.42(PB6)
SWIM_RST_IN: U2.41(PB5)
T_JTCK: R14.2 SB4.1 U2.15(PA5) U2.26(PB13)
T_JTDI: U2.17(PA7)
T_JTDO: U2.16(PA6)
T_JTMS: R15.2 R16.2 SB8.1 U2.27(PB14)
T_NRST: R17.2 SB12.1 U2.18(PB0)
T_SWDIO_IN: R16.1 U2.25(PB12)
T_SWO: R20.2 SB9.1 U2.31(PA10)
USB_DM: R12.2 U2.32(PA11)
USB_DP: R11.2 U2.33(PA12)
NetC3_2: C3.2 U1.4(BYPASS)
NetC5_1: C5.1 C6.2 D3.1(A) U1.5(Vout)
NetCN1_2: CN1.2(D-) R12.1
NetCN1_3: CN1.3(D+) R10.1 R11.1
NetCN1_4: CN1.4(ID) R9.1
NetCN2_1: CN2.1 D1.1(A) R5.1
NetCN2_2: CN2.2 R14.1
NetCN2_4: CN2.4 R15.1
NetCN2_5: CN2.5 R17.1
NetCN2_6: CN2.6 R20.1
NetCN4_1: CN4.1 SB3.1 SB4.2
NetCN4_2: CN4.2 SB5.1 SB6.2
NetCN4_3: CN4.3 SB7.1 SB8.2
NetCN4_4: CN4.4 SB13.1 SB14.2
NetD1_2: D1.2(K) R13.1
NetLD1_2: LD1.2 R2.2
NetLD1_3: LD1.3 R1.2
NetLD1_4: LD1.4 R3.1
NetLD2_1: LD2.1 R4.1
NetR6_2: R6.2 U2.3(PC14)
NetR7_2: R7.2 U2.2(PC13)
NetR8_2: R8.2 U2.44(BOOT0)
NetR28_1: R28.1 U2.29(PA8)

Not connected (* = marked no-connect by the designer): U2 4(PC15)* 11(PA1)* 14(PA4)* 19(PB1)* 28(PB15)* 38(PA15/JTDI)* 39(PB3/JTDO)* 40(PB4/JNTRST)*

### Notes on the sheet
- TCK/SWCLK
- (near SB9) TMS/SWDIO
- SWD
- Board Ident: PC13=0
- Not Fitted
- SWCLK
- SWDIO
- (near R28) RC Must be very close to STM32F103 pin 29
- Jumpers ON  --> DISCOVERY Selected
  Jumpers OFF --> ST-LINK Selected
- STM32F4_USART1_RX
- TX
- (near JP3) Idd
- COM
- STM32F4_USART1_TX
- RX
- (near U2) T_JRST
- Close to JP
- (near U1) PWR
- USB ST-LINK
- (near D2) EXT_5V, Input only
- EXT_3V, Input only
- STM32F429I-DISCO ST-LINK/V2 (SWD only)
- MB1075

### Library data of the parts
C1 C4 C6 C9 C27 C46 C47 = Capacitor_ST: Capacitor 0402 / 0603 / 0805
C2 C5 = CAP SMD 0603  X5R 1µF 25V 10%: 0603  X5R 1µF; Rated voltage: 25V; Tolerance: 10%
C3 = CAP SMD 0603  X7R 10000PF 50V 10%: 0603  X7R 10NF; Order code RS: 2040779; Rated voltage: 50V; Tolerance: 10%
C16 C17 = Capacitor_ST: as C20 on sheet STM32Fx
C18 = Capacitor_ST: as C23 on sheet STM32Fx
CN1 = USB-MINI-typeB connector: Manuf_Part_1: 5075BMR-05-SM; Manuf_Part_2: 218205M1110T; Manuf_2: lyconn; Description: USB,MINI-USB-5P/F, 5075BMR-05-M
CN2 = Header 6: Header, 6-Pin
CN4 = Header 4: Header, 4-Pin
D1-D3 = BAT60JFILM: Manuf_1: STM; Provided: ST; ECCN_US/EU: EAR99/NEC
JP1-JP3 = JP2
JP4 = JP2: Fitted: NO
LD1 = LD_BICOLOR_CMS: Bicolor Led; Manuf_Part_1: HSMF-A201-A00J1; Manuf_1: Avago Technologies; Manuf_2: everluck; Manuf_Part_2: LE-RGW35280; Ref St: xxxxxx
LD2 = LED_red: LED, red, 0603; Manuf_1: everlight; Manuf_Part_1: 19-213-R6C-AP1Q2B/3T; Description: LED,red,0603,19-213-R6C-AP1Q2B/3T,everlight
R1-R4 R8-R12 R14-R21 R28 = Resistor_ST: as R22 on sheet IO Peripherals
R5 R7 = Resistor_ST: as R71 on sheet USB_OTG_FS
R6 = Resistor_ST: Resistor 0402 / 0603 / 0805; Description: Resistor 0402 or 0603 or 0805; Fitted: NO
R13 = Resistor_ST: as R53 on sheet STM32Fx
SB3 SB5 SB7 SB12 SB13 = Circuit Breaker: Solder: YES
SB4 SB6 SB8-SB11 SB14 SB15 = Circuit Breaker: Solder: NO
U1 = LD3985M33R: Ultra low drop-low noise BiCMOS voltage, regulators low ESR capacitors compatible; Manuf_1: STM; Provided: ST; Ref St: 9176161; ECCN_US/EU: EAR99/NEC
U2 = STM32F103C8T6: Medium-density performance line ARM-based 32-bit MCU with 64KB Flash; Manuf_1: STM; Ref St: 9175981; Provided: ST; ECCN_US/EU: 3A991A2/NEC
X1 = XTAL: as X3 on sheet STM32Fx

## Sheet LCD-24.SchDoc
size A4; DocumentNumber: 7; Revision: B.1(PCB.SCH); SheetNumber: 7; SheetTotal: 7
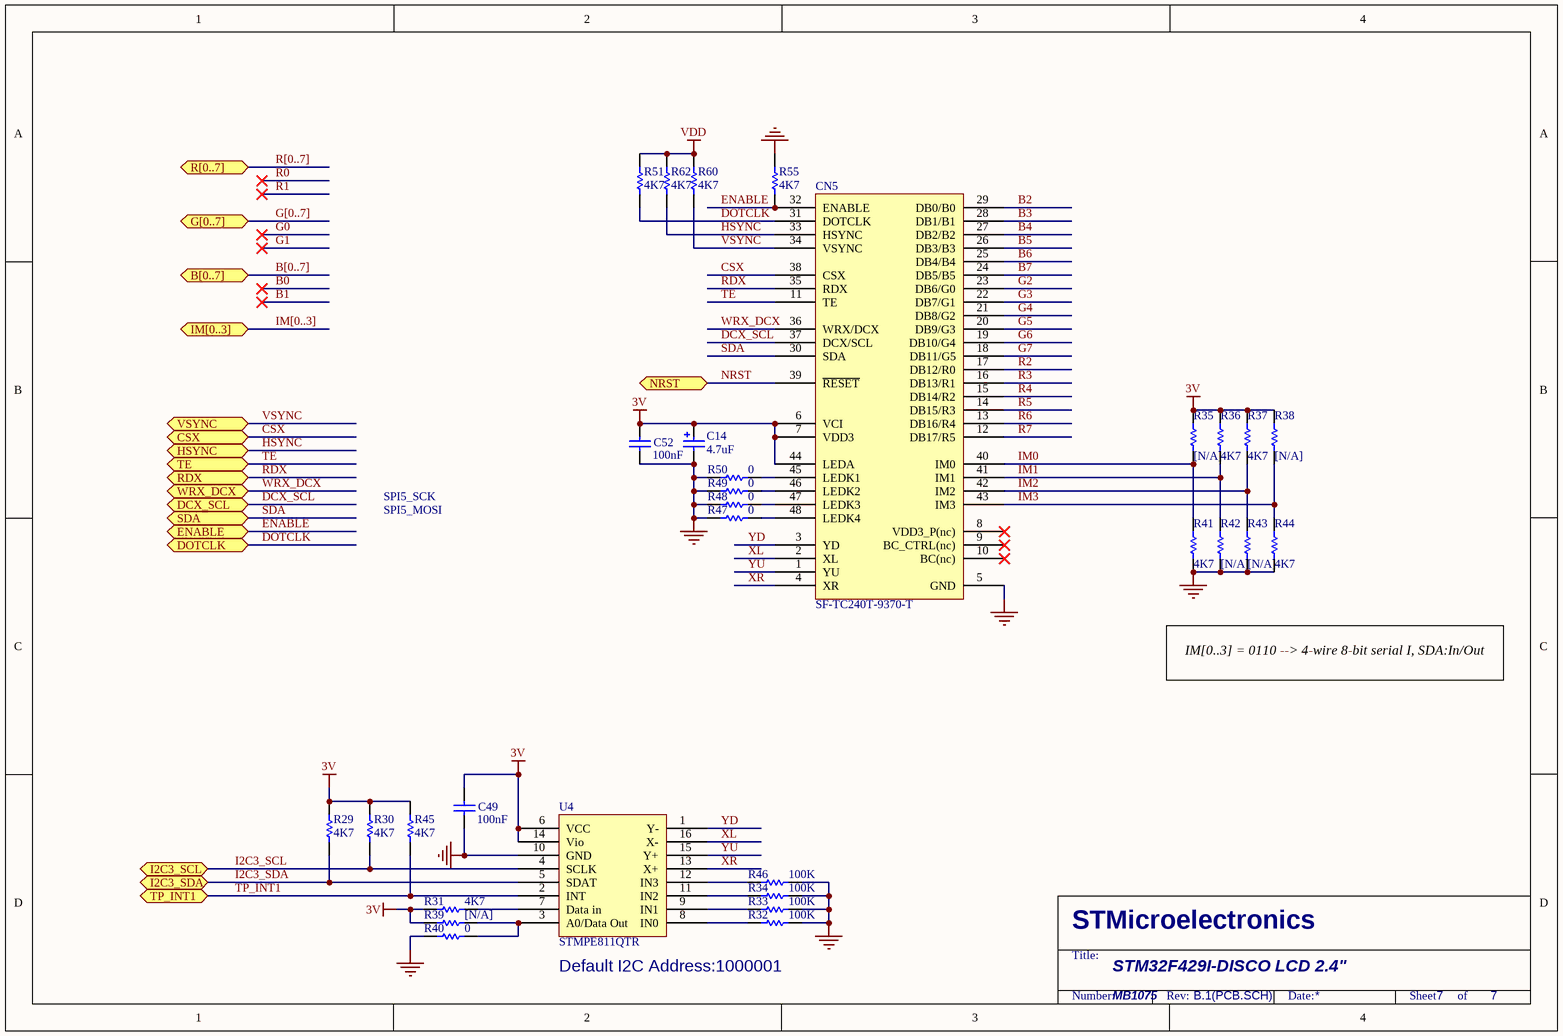
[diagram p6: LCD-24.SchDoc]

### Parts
C14  4.7uF  [TAN-A]
C49  100nF  [0402C]
C52  100nF  [0402C]
CN5  SF-TC240T-9370-T  [SF-TC240T-48P-07]
R29  4K7  [0402R]
R30  4K7  [0402R]
R31  4K7  [0402R]
R32  100K  [0402R]
R33  100K  [0402R]
R34  100K  [0402R]
R35  [N/A]  [0402R]
R36  4K7  [0402R]
R37  4K7  [0402R]
R38  [N/A]  [0402R]
R39  [N/A]  [0402R]
R40  0  [0402R]
R41  4K7  [0402R]
R42  [N/A]  [0402R]
R43  [N/A]  [0402R]
R44  4K7  [0402R]
R45  4K7  [0402R]
R46  100K  [0402R]
R47  0  [0603R]
R48  0  [0603R]
R49  0  [0603R]
R50  0  [0603R]
R51  4K7  [0402R]
R55  4K7  [0402R]
R60  4K7  [0402R]
R62  4K7  [0402R]
U4  STMPE811QTR  [QFN16_3X3]

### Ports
B[0..7], CSX, DCX_SCL, DOTCLK, ENABLE, G[0..7], HSYNC, I2C3_SCL, I2C3_SDA, IM[0..3], NRST, R[0..7], RDX, SDA, TE, TP_INT1, VSYNC, WRX_DCX

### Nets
3V: C14.1 C49.2 C52.2 CN5.6(VCI) CN5.7(VDD3) CN5.44(LEDA) R29.2 R30.2 R31.1 R35.2 R36.2 R37.2 R38.2 R39.1 R45.2 U4.6(VCC) U4.14(Vio)
GND: C14.2 C49.1 C52.1 CN5.5(GND) R32.2 R33.2 R34.2 R40.1 R41.1 R42.1 R43.1 R44.1 R46.2 R47.1 R48.1 R49.1 R50.1 R55.2 U4.10(GND)
VDD: R51.2 R60.2 R62.2
B2: CN5.29(DB0/B0)
B3: CN5.28(DB1/B1)
B4: CN5.27(DB2/B2)
B5: CN5.26(DB3/B3)
B6: CN5.25(DB4/B4)
B7: CN5.24(DB5/B5)
CSX: CN5.38(CSX) ; port CSX
DCX_SCL: CN5.37(DCX/SCL) ; port DCX_SCL
DOTCLK: CN5.31(DOTCLK) R51.1 ; port DOTCLK
ENABLE: CN5.32(ENABLE) R55.1 ; port ENABLE
G2: CN5.23(DB6/G0)
G3: CN5.22(DB7/G1)
G4: CN5.21(DB8/G2)
G5: CN5.20(DB9/G3)
G6: CN5.19(DB10/G4)
G7: CN5.18(DB11/G5)
HSYNC: CN5.33(HSYNC) R62.1 ; port HSYNC
I2C3_SCL: R30.1 U4.4(SCLK) ; port I2C3_SCL
I2C3_SDA: R29.1 U4.5(SDAT) ; port I2C3_SDA
IM0: CN5.40(IM0) R35.1 R41.2
IM1: CN5.41(IM1) R36.1 R42.2
IM2: CN5.42(IM2) R37.1 R43.2
IM3: CN5.43(IM3) R38.1 R44.2
NRST: CN5.39(~{RESET}) ; port NRST
R2: CN5.17(DB12/R0)  [project net PC10]
R3: CN5.16(DB13/R1)  [project net PB0]
R4: CN5.15(DB14/R2)  [project net PA11]
R5: CN5.14(DB15/R3)  [project net PA12]
R6: CN5.13(DB16/R4)  [project net PB1]
R7: CN5.12(DB17/R5)  [project net PG6]
RDX: CN5.35(RDX) ; port RDX  [project net PD12]
SDA: CN5.30(SDA) ; port SDA  [project net PF9]
TE: CN5.11(TE) ; port TE  [project net PD11]
TP_INT1: R45.1 U4.2(INT) ; port TP_INT1  [project net PA15]
VSYNC: CN5.34(VSYNC) R60.1 ; port VSYNC  [project net PA4]
WRX_DCX: CN5.36(WRX/DCX) ; port WRX_DCX  [project net PD13]
XL: CN5.2(XL) U4.16(X-)
XR: CN5.4(XR) U4.13(X+)
YD: CN5.3(YD) U4.1(Y-)
YU: CN5.1(YU) U4.15(Y+)
NetCN5_45: CN5.45(LEDK1) R50.2
NetCN5_46: CN5.46(LEDK2) R49.2
NetCN5_47: CN5.47(LEDK3) R48.2
NetCN5_48: CN5.48(LEDK4) R47.2
NetR31_2: R31.2 U4.7(Data_in)
NetR32_1: R32.1 U4.8(IN0)
NetR33_1: R33.1 U4.9(IN1)
NetR34_1: R34.1 U4.11(IN2)
NetR39_2: R39.2 R40.2 U4.3(A0/Data_Out)
NetR46_1: R46.1 U4.12(IN3)

Not connected (* = marked no-connect by the designer): CN5 8(VDD3_P(nc))* 9(BC_CTRL(nc))* 10(BC(nc))*

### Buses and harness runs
bus B[0..7] = port B[0..7]
bus G[0..7] = port G[0..7]
bus IM[0..3] = port IM[0..3]
bus R[0..7] = port R[0..7]

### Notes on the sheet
- SPI5_MOSI
- SPI5_SCK
- IM[0..3] = 0110 --> 4-wire 8-bit serial I, SDA:In/Out
- Default I2C Address:1000001
- STM32F429I-DISCO LCD 2.4"
- MB1075

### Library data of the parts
C14 = Cap Pol1: Polarized Capacitor (Radial); Value: 100pF
C49 C52 = Capacitor_ST: Capacitor 0402 / 0603 / 0805
CN5 = SF-TC240T-9370-T: 2.4" LCD TFT 320x240 with Touch Panel; Manuf_1: SAEF
R29-R34 R36 R37 R40 R41 R44-R51 R55 R60 R62 = Resistor_ST: as R22 on sheet IO Peripherals
R35 R38 R39 R42 R43 = Resistor_ST: as R53 on sheet STM32Fx
U4 = STMPE811: S-Touch® advanced resistive touchscreen controller, with 8-bit GPIO expander; Manuf_1: STM; Provided: ST; Ref St: xxxxxxxx; ECCN_US/EU: EAR99/NEC

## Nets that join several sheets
3V: MB1075 (P2.1 P2.2), SDRAM (14 pins), IO Peripherals (6 pins), USB_OTG_FS (R68.2 R70.2 R71.2 R73.2), ST_LINK_V2 (17 pins), LCD-24 (17 pins)
5V: MB1075 (P1.1 P1.2), IO Peripherals (CN3.8), USB_OTG_FS (U8.5), ST_LINK_V2 (5 pins)
GND: MB1075 (6 pins), SDRAM (14 pins), IO Peripherals (16 pins), STM32Fx (35 pins), USB_OTG_FS (7 pins), ST_LINK_V2 (36 pins), LCD-24 (19 pins)
VDD: MB1075 (P1.22), IO Peripherals (B1.1 B1.4 R24.2 R25.2), STM32Fx (29 pins), ST_LINK_V2 (JP3.2), LCD-24 (R51.2 R60.2 R62.2)
A0: MB1075 (P1.7), SDRAM (U6.23), STM32Fx (U5.10)
A1: MB1075 (P1.8), SDRAM (U6.24), STM32Fx (U5.11)
A2: MB1075 (P1.5), SDRAM (U6.25), STM32Fx (U5.12)
A3: MB1075 (P1.6), SDRAM (U6.26), STM32Fx (U5.13)
A4: MB1075 (P1.3), SDRAM (U6.29), STM32Fx (U5.14)
A5: MB1075 (P1.4), SDRAM (U6.30), STM32Fx (U5.15)
A6: MB1075 (P2.31), SDRAM (U6.31), STM32Fx (U5.50)
A7: MB1075 (P2.34), SDRAM (U6.32), STM32Fx (U5.53)
A8: MB1075 (P2.33), SDRAM (U6.33), STM32Fx (U5.54)
A9: MB1075 (P2.36), SDRAM (U6.34), STM32Fx (U5.55)
A10: MB1075 (P2.35), SDRAM (U6.22), STM32Fx (U5.56)
A11: MB1075 (P2.38), SDRAM (U6.35), STM32Fx (U5.57)
ACP_RST: MB1075 (P2.23), IO Peripherals (CN3.4), STM32Fx (U5.43)
B2: MB1075 (P1.36), STM32Fx (U5.122), LCD-24 (CN5.29)
B3: MB1075 (P1.31), STM32Fx (U5.126), LCD-24 (CN5.28)
B4: MB1075 (P1.32), STM32Fx (U5.127), LCD-24 (CN5.27)
B5: MB1075 (P2.19), STM32Fx (U5.37), LCD-24 (CN5.26)
B6: MB1075 (P1.19), STM32Fx (U5.139), LCD-24 (CN5.25)
B7: MB1075 (P1.20), STM32Fx (U5.140), LCD-24 (CN5.24)
BA0: MB1075 (P1.62), SDRAM (U6.20), STM32Fx (U5.89)
BA1: MB1075 (P1.61), SDRAM (U6.21), STM32Fx (U5.90)
BOOT0: MB1075 (P1.21), STM32Fx (R59.2 R61.2 U5.138)
CSX: MB1075 (P2.16), STM32Fx (U5.28), LCD-24 (CN5.38)
D0: MB1075 (P2.60), SDRAM (U6.2), STM32Fx (U5.85)
D1: MB1075 (P2.59), SDRAM (U6.4), STM32Fx (U5.86)
D2: MB1075 (P1.42), SDRAM (U6.5), STM32Fx (U5.114)
D3: MB1075 (P1.41), SDRAM (U6.7), STM32Fx (U5.115)
D4: MB1075 (P2.37), SDRAM (U6.8), STM32Fx (U5.58)
D5: MB1075 (P2.40), SDRAM (U6.10), STM32Fx (U5.59)
D6: MB1075 (P2.39), SDRAM (U6.11), STM32Fx (U5.60)
D7: MB1075 (P2.42), SDRAM (U6.13), STM32Fx (U5.63)
D8: MB1075 (P2.41), SDRAM (U6.42), STM32Fx (U5.64)
D9: MB1075 (P2.44), SDRAM (U6.44), STM32Fx (U5.65)
D10: MB1075 (P2.43), SDRAM (U6.45), STM32Fx (U5.66)
D11: MB1075 (P2.46), SDRAM (U6.47), STM32Fx (U5.67)
D12: MB1075 (P2.45), SDRAM (U6.48), STM32Fx (U5.68)
D13: MB1075 (P2.54), SDRAM (U6.50), STM32Fx (U5.77)
D14: MB1075 (P2.53), SDRAM (U6.51), STM32Fx (U5.78)
D15: MB1075 (P2.56), SDRAM (U6.53), STM32Fx (U5.79)
DCX_SCL: MB1075 (P2.6), IO Peripherals (U3.2), STM32Fx (U5.19), LCD-24 (CN5.37)
DOTCLK: MB1075 (P1.59), STM32Fx (U5.92), LCD-24 (CN5.31 R51.1)
ENABLE: MB1075 (P2.7), STM32Fx (U5.22), LCD-24 (CN5.32 R55.1)
G2: MB1075 (P2.24), STM32Fx (U5.42), LCD-24 (CN5.23)
G3: MB1075 (P1.34), STM32Fx (U5.125), LCD-24 (CN5.22)
G4: MB1075 (P2.48), STM32Fx (U5.69), LCD-24 (CN5.21)
G5: MB1075 (P2.47), STM32Fx (U5.70), LCD-24 (CN5.20)
G6: MB1075 (P1.56), STM32Fx (U5.97), LCD-24 (CN5.19)
G7: MB1075 (P1.39), STM32Fx (U5.117), LCD-24 (CN5.18)
HSYNC: MB1075 (P1.57), STM32Fx (U5.96), LCD-24 (CN5.33 R62.1)
I2C3_SCL: MB1075 (P1.53), IO Peripherals (CN3.3), STM32Fx (U5.100), LCD-24 (R30.1 U4.4)
I2C3_SDA: MB1075 (P1.54), IO Peripherals (CN3.1), STM32Fx (U5.99), LCD-24 (R29.1 U4.5)
IM0: STM32Fx (SB25.2), LCD-24 (CN5.40 R35.1 R41.2)
IM1: STM32Fx (SB24.2), LCD-24 (CN5.41 R36.1 R42.2)
IM2: STM32Fx (SB23.2), LCD-24 (CN5.42 R37.1 R43.2)
IM3: STM32Fx (SB22.2), LCD-24 (CN5.43 R38.1 R44.2)
MCO: STM32Fx (SB18.1), ST_LINK_V2 (C18.2 R28.2)
MEMS_INT1: MB1075 (P2.17), IO Peripherals (U3.7), STM32Fx (U5.35)
MEMS_INT2: MB1075 (P2.20), IO Peripherals (U3.6), STM32Fx (U5.36)
NBL0: MB1075 (P1.17), SDRAM (U6.15), STM32Fx (U5.141)
NBL1: MB1075 (P1.18), SDRAM (U6.39), STM32Fx (U5.142)
NCS_MEMS_SPI: MB1075 (P2.13), IO Peripherals (U3.5), STM32Fx (U5.27)
NRST: MB1075 (P2.12), IO Peripherals (SB1.1), STM32Fx (U5.25), ST_LINK_V2 (SB12.2), LCD-24 (CN5.39)
OTG_FS_DM: MB1075 (SB27.2), STM32Fx (U5.75), USB_OTG_FS (R64.1 U7.D3)
OTG_FS_DP: MB1075 (SB26.1), STM32Fx (U5.76), USB_OTG_FS (R63.1 U7.C3)
OTG_FS_ID: MB1075 (P2.50), STM32Fx (U5.73), USB_OTG_FS (R67.1)
OTG_FS_OC: MB1075 (P2.25), STM32Fx (U5.45), USB_OTG_FS (R69.2)
OTG_FS_PSO: MB1075 (P2.26), STM32Fx (U5.44), USB_OTG_FS (R72.1)
PA0: MB1075 (P2.18), IO Peripherals (SB2.1), STM32Fx (U5.34)
PA4: MB1075 (P2.22), STM32Fx (U5.40), LCD-24 (CN5.34 R60.1)
PA5: MB1075 (P2.21), STM32Fx (U5.41)
PA9: MB1075 (P1.52), STM32Fx (U5.101), ST_LINK_V2 (SB11.1)
PA10: MB1075 (P1.51), STM32Fx (U5.102), ST_LINK_V2 (SB15.1)
PA11: MB1075 (P1.50), STM32Fx (U5.103), LCD-24 (CN5.15)
PA12: MB1075 (P1.49), STM32Fx (U5.104), LCD-24 (CN5.14)
PA13: MB1075 (P1.48), STM32Fx (U5.105), ST_LINK_V2 (SB14.1)
PA14: MB1075 (P1.47), STM32Fx (U5.109), ST_LINK_V2 (SB6.1)
PA15: MB1075 (P1.46), STM32Fx (U5.110), LCD-24 (R45.1 U4.2)
PB0: MB1075 (P2.28), STM32Fx (U5.46), LCD-24 (CN5.16)
PB1: MB1075 (P2.27), STM32Fx (U5.47), LCD-24 (CN5.13)
PB2: MB1075 (P2.30), STM32Fx (U5.48)
PB3: MB1075 (P1.28), STM32Fx (U5.133), ST_LINK_V2 (SB9.2)
PB4: MB1075 (P1.25), STM32Fx (U5.134)
PB5: MB1075 (P1.26), SDRAM (U6.37), STM32Fx (U5.135)
PB6: MB1075 (P1.23), SDRAM (U6.19), STM32Fx (U5.136)
PB7: MB1075 (P1.24), STM32Fx (U5.137)
PB13: MB1075 (P2.49), STM32Fx (U5.74), USB_OTG_FS (5 pins)
PC0: MB1075 (P2.14), SDRAM (U6.16), STM32Fx (U5.26)
PC3: MB1075 (P2.15), STM32Fx (U5.29)
PC8: MB1075 (P1.55), STM32Fx (U5.98)
PC10: MB1075 (P1.45), STM32Fx (U5.111), LCD-24 (CN5.17)
PC11: MB1075 (P1.44), STM32Fx (U5.112)
PC12: MB1075 (P1.43), STM32Fx (U5.113)
PC13: MB1075 (P1.12), STM32Fx (U5.7)
PC14: MB1075 (P1.9), STM32Fx (SB16.1)
PC15: MB1075 (P1.10), STM32Fx (SB17.1)
PD2: MB1075 (P1.40), STM32Fx (SB25.1 U5.116)
PD4: MB1075 (P1.38), STM32Fx (SB24.1 U5.118)
PD5: MB1075 (P1.37), STM32Fx (SB23.1 U5.119)
PD7: MB1075 (P1.35), STM32Fx (SB22.1 U5.123)
PD11: MB1075 (P2.55), STM32Fx (U5.80), LCD-24 (CN5.11)
PD12: MB1075 (P2.58), STM32Fx (U5.81), LCD-24 (CN5.35)
PD13: MB1075 (P2.57), STM32Fx (U5.82), LCD-24 (CN5.36)
PE2: MB1075 (P1.15), STM32Fx (U5.1)
PE3: MB1075 (P1.16), STM32Fx (U5.2)
PE4: MB1075 (P1.13), STM32Fx (U5.3)
PE5: MB1075 (P1.14), STM32Fx (U5.4)
PE6: MB1075 (P1.11), STM32Fx (U5.5)
PF6: MB1075 (P2.3), STM32Fx (U5.18)
PF8: MB1075 (P2.5), IO Peripherals (U3.4), STM32Fx (U5.20)
PF9: MB1075 (P2.8), IO Peripherals (U3.3), STM32Fx (U5.21), LCD-24 (CN5.30)
PF11: MB1075 (P2.32), SDRAM (U6.18), STM32Fx (U5.49)
PG2: MB1075 (P2.62), STM32Fx (U5.87)
PG3: MB1075 (P2.61), STM32Fx (U5.88)
PG6: MB1075 (P1.60), STM32Fx (U5.91), LCD-24 (CN5.12)
PG8: MB1075 (P1.58), SDRAM (U6.38), STM32Fx (U5.93)
PG9: MB1075 (P1.33), STM32Fx (U5.124)
PG13: MB1075 (P1.29), IO Peripherals (R26.1), STM32Fx (U5.128)
PG14: MB1075 (P1.30), IO Peripherals (R27.1), STM32Fx (U5.129)
PG15: MB1075 (P1.27), SDRAM (U6.17), STM32Fx (U5.132)
PH0: MB1075 (P2.10), STM32Fx (SB19.1)
PH1: MB1075 (P2.9), STM32Fx (SB20.1)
